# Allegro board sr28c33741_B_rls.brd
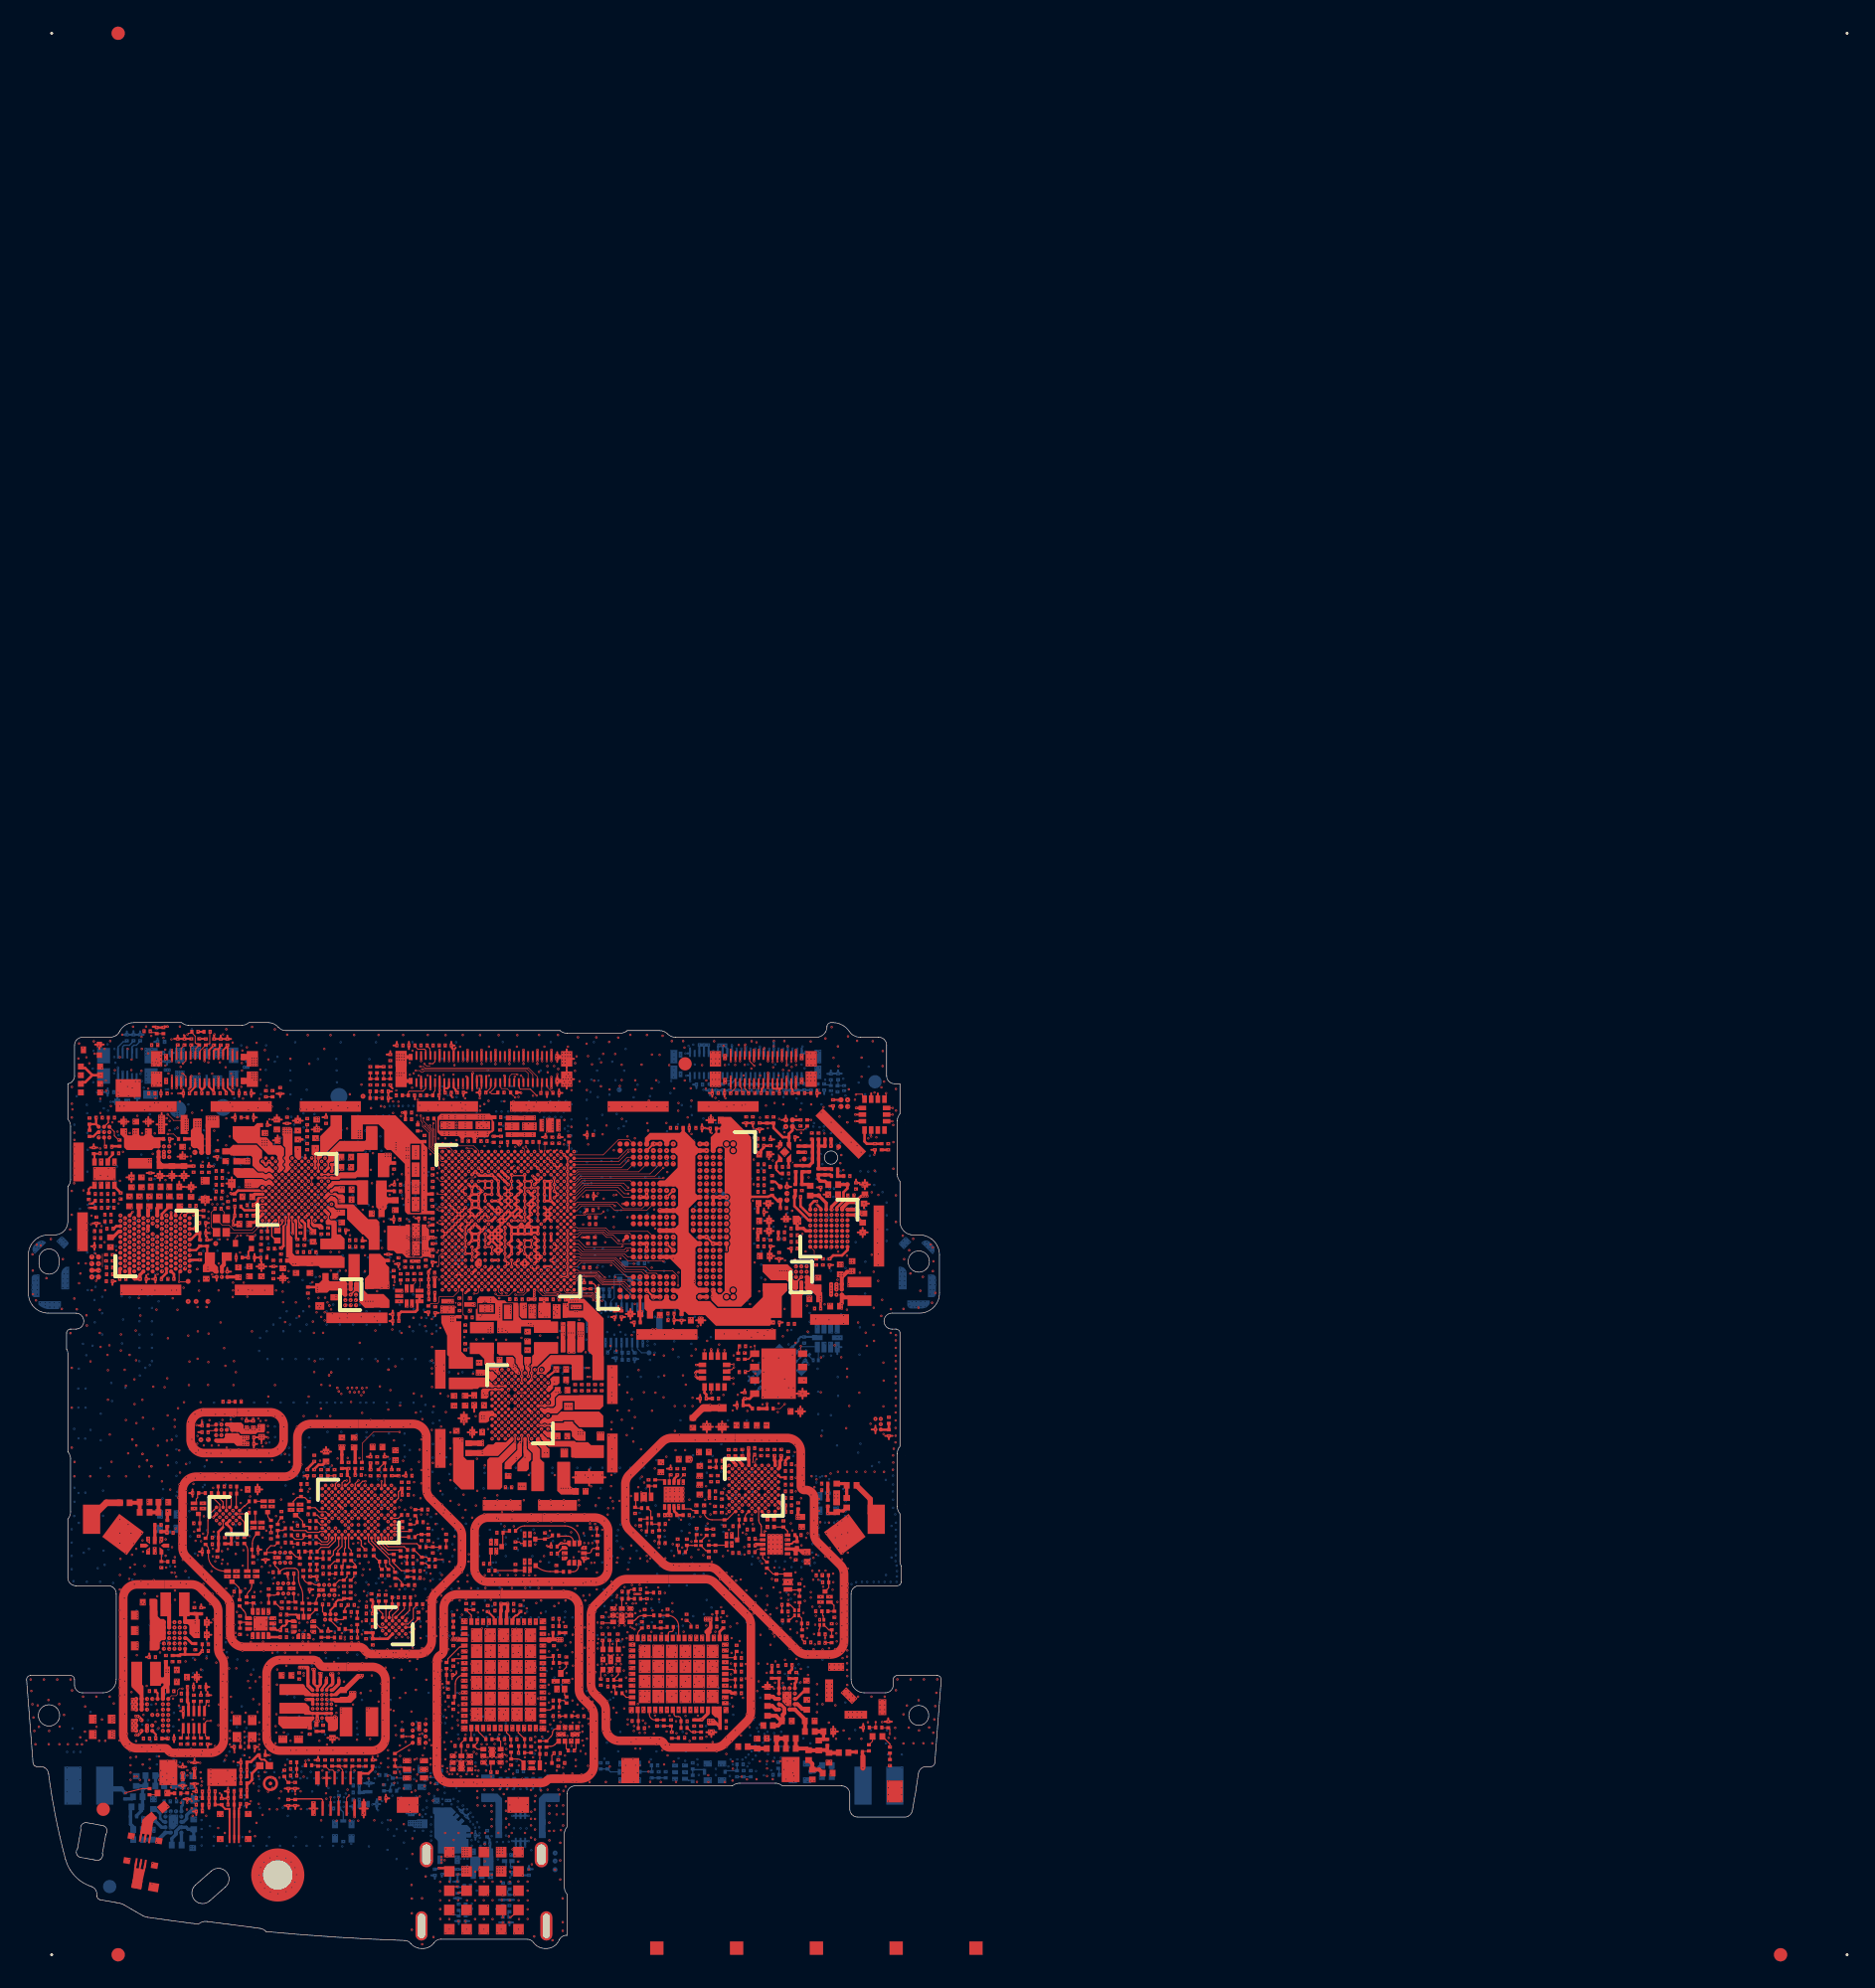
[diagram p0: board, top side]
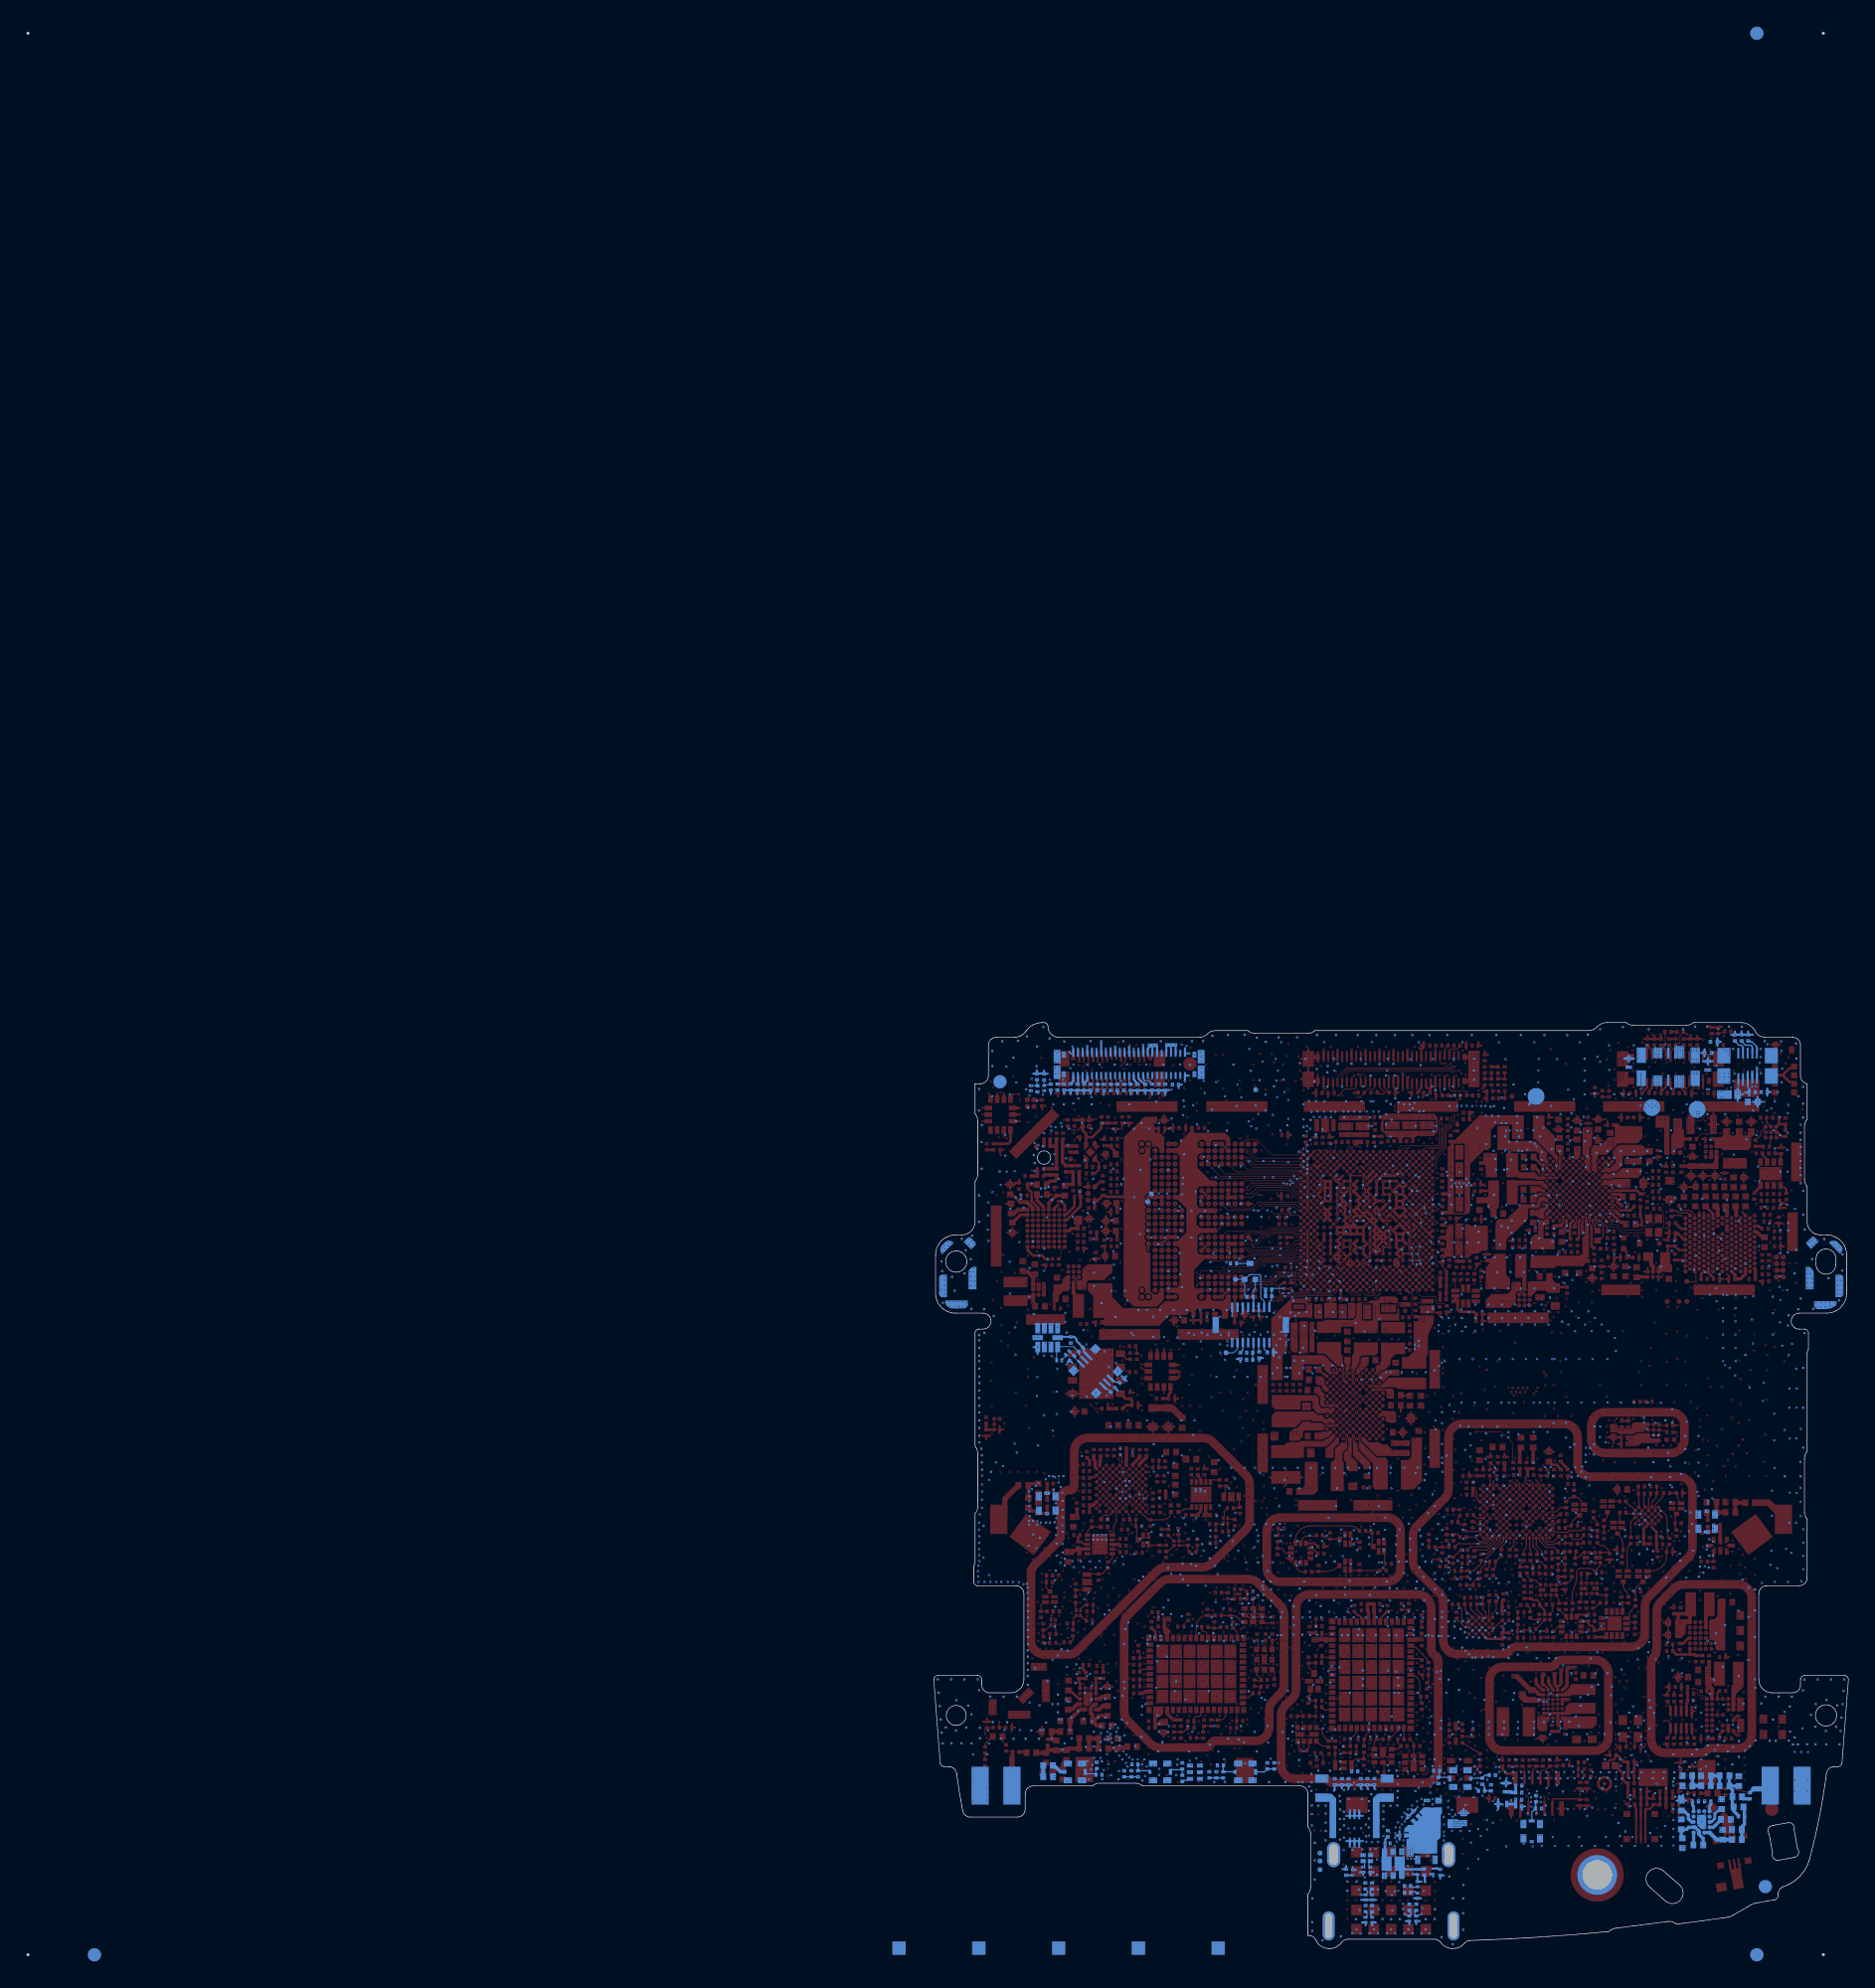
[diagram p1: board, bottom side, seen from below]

Outline 68.77 x 69.63 mm; copper layers: TOP, LAYER_2, LAYER_3, LAYER_4, LAYER_5, LAYER_6, LAYER_7, BOTTOM. Coordinates in mm from the lower left corner of the outline.

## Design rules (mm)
constraint set DEFAULT: min track width 0.05, pair gap 0.05
net group CXM_CMD: nets CXM_CMD<0> CXM_CMD<1>
net group DISP_SUP_DSI1_1_DP: nets DISP_SUB_DSI1<0> DISP_SUB_DSI1<1>
net group DISP_SUP_DSI1_2_DP: nets DISP_SUB_DSI1<2> DISP_SUB_DSI1<3>
net group DISP_SUP_DSI1_3_DP: nets DISP_SUB_DSI1<4> DISP_SUB_DSI1<5>
net group DP_MIPI_CSI_REAR_1: nets MIPI_CSI_REAR<0> MIPI_CSI_REAR<1>
net group DP_MIPI_CSI_REAR_2: nets MIPI_CSI_REAR<2> MIPI_CSI_REAR<3>
net group DP_MIPI_CSI_REAR_3: nets MIPI_CSI_REAR<4> MIPI_CSI_REAR<5>
net group DP_MIPI_CSI_REAR_4: nets MIPI_CSI_REAR<6> MIPI_CSI_REAR<7>
net group DP_MIPI_CSI_REAR_5: nets MIPI_CSI_REAR<8> MIPI_CSI_REAR<9>
net group DSBC_DP: nets USBC_DM USBC_DP
net group EBI0_DM: nets EBI0_DM<0> EBI0_DM<1>
net group EBI1_DM: nets EBI1_DM<0> EBI1_DM<1>
net group HIGH SPEED SSTX1: nets SSTX1_DM SSTX1_DP
net group HIGH SPEED SSTX2: nets SSTX2_DM SSTX2_DP
net group HIGH SPEED USB HS C: nets USB_HS_C_DM USB_HS_C_DP
net group MIPI_CSI2_1_DP: nets MIPI_CSI2_CLK_M MIPI_CSI2_CLK_P
net group MIPI_CSI2_2_DP: nets MIPI_CSI2_LANE0_M MIPI_CSI2_LANE0_P
net group MIPI_CSI2_3_DP: nets MIPI_CSI2_LANE1_M MIPI_CSI2_LANE1_P
net group MIPI_CSI2_4_DP: nets MIPI_CSI2_LANE2_M MIPI_CSI2_LANE2_P
net group MIPI_CSI2_5_DP: nets MIPI_CSI2_LANE3_M MIPI_CSI2_LANE3_P
net group MIPI_CSI_FRONT_1_DP: nets MIPI_CSI_FRONT<0> MIPI_CSI_FRONT<1>
net group MIPI_CSI_FRONT_2_DP: nets MIPI_CSI_FRONT<2> MIPI_CSI_FRONT<3>
net group MIPI_CSI_FRONT_3_DP: nets MIPI_CSI_FRONT<4> MIPI_CSI_FRONT<5>
net group MIPI_DSI0_1_DP: nets MIPI_DSI0<0> MIPI_DSI0<1>
net group MIPI_DSI0_2_DP: nets MIPI_DSI0<2> MIPI_DSI0<3>
net group MIPI_DSI0_3_DP: nets MIPI_DSI0<4> MIPI_DSI0<5>
net group MIPI_DSI0_4_DP: nets MIPI_DSI0<6> MIPI_DSI0<7>
net group MIPI_DSI0_5_DP: nets MIPI_DSI0<8> MIPI_DSI0<9>
net group MSS_CMD: nets MSS_CMD<0> MSS_CMD<1>
net group QLINK_CLK_DP: nets QLINK_CLK_M QLINK_CLK_P
net group QLINK_RX0_DP: nets QLINK_RX0_M QLINK_RX0_P
net group QLINK_RX1_DP: nets QLINK_RX1_M QLINK_RX1_P
net group QLINK_RX2_DP: nets QLINK_RX2_M QLINK_RX2_P
net group QLINK_TX_DP: nets QLINK_TX_M QLINK_TX_P
net group USBC_RX1_DP: nets USBC_RX1_DM USBC_RX1_DP
net group USBC_RX2_DP: nets USBC_RX2_DM USBC_RX2_DP
net group USBC_TX1_DP: nets USBC_TX1_DM USBC_TX1_DP
net group USBC_TX2_DP: nets USBC_TX2_DM USBC_TX2_DP
net group WL_BB_DP1: nets WL_BB<0> WL_BB<1>
net group WL_BB_DP2: nets WL_BB<2> WL_BB<3>
net group WL_BB_DP3: nets WL_BB<4> WL_BB<5>
net group WL_BB_DP4: nets WL_BB<6> WL_BB<7>
net group EBI0_CA: nets EBI0_CA<0> EBI0_CA<1> EBI0_CA<2> EBI0_CA<3> EBI0_CA<4> EBI0_CA<5>
net group EBI0_DQ: nets EBI0_DQ<0> EBI0_DQ<1> EBI0_DQ<2> EBI0_DQ<3> EBI0_DQ<4> EBI0_DQ<5> EBI0_DQ<6> EBI0_DQ<7> EBI0_DQ<8> EBI0_DQ<9> EBI0_DQ<10> EBI0_DQ<11> EBI0_DQ<12> EBI0_DQ<13> EBI0_DQ<14> EBI0_DQ<15>
net group EBI1_CA: nets EBI1_CA<0> EBI1_CA<1> EBI1_CA<2> EBI1_CA<3> EBI1_CA<4> EBI1_CA<5>
net group EBI1_DQ: nets EBI1_DQ<0> EBI1_DQ<1> EBI1_DQ<2> EBI1_DQ<3> EBI1_DQ<4> EBI1_DQ<5> EBI1_DQ<6> EBI1_DQ<7> EBI1_DQ<8> EBI1_DQ<9> EBI1_DQ<10> EBI1_DQ<11> EBI1_DQ<12> EBI1_DQ<13> EBI1_DQ<14> EBI1_DQ<15>
net group POWER_LN: nets B_PLUS BATT_PLUS USB_PWR
net group RF_50_OHM: nets GPS_LNA_IN_50R GPS_LNA_OUT_50R WTR0_GPS_A_50R
net group WL_CMD: nets WL_CMD<0> WL_CMD<1> WL_CMD<2> WL_CMD<3>

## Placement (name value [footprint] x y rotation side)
C100  100PF  [CAP0201-HT0_33_HD]  12.99 11.81 0 top
C102  .1UF  [CAP0201-HT0_33_HD]  11.5 11.06 0 bottom
C103  .1UF  [CAP0201-HT0_33_HD]  10.58 11.05 180 bottom
C105  100PF  [CAP0201-HT0_33_HD]  12.99 10.31 0 top
C110  100PF  [CAP0201-HT0_33_HD]  23.49 11.27 270 bottom
C112  10NH  [IND1005-HT0_6_HD]  12.56 9.34 270 bottom
C115  1.5e-005 uF  [CAP0402-HT0_55_HD]  11.29 7.78 0 bottom
C121  91NH  [IND1005-HT0_6_HD]  9.46 8.56 270 bottom
C124  4.3NH  [IND1005-HT0_6_HD]  8.26 10.65 0 bottom
C130  33PF  [CAP0201-HT0_33_HD]  30.97 13.37 180 bottom
C132  100PF  [CAP0201-HT0_33_HD]  26.88 12.08 270 bottom
C133  33PF  [CAP0201-HT0_33_HD]  26.78 13.04 180 bottom
C140  0  [RES0402-HT0_4_HD]  12.11 12.99 180 bottom
C141  6.2NH  [IND1005-HT0_6_HD]  12.1 12.23 180 bottom
C144  8.2NH  [IND1005-HT0_6_HD]  9.31 13 180 bottom
C172  100PF  [CAP0201-HT0_33_HD]  7.41 11.48 90 bottom
C174  1.5PF  [CAP0201-HT0_33_HD]  12.08 11.47 90 top
C200  100PF  [CAP0201-HT0_33_HD]  56.28 21.26 180 top
C202  .1UF  [CAP0201-HT0_33_HD]  56.58 20.55 270 top
C203  .1UF  [CAP0201-HT0_33_HD]  57.87 20.53 270 top
C205  100PF  [CAP0201-HT0_33_HD]  57.33 21.32 0 top
C210  100PF  [CAP0201-HT0_33_HD]  50.09 12.79 90 bottom
C212  100PF  [CAP0201-HT0_33_HD]  53.92 13.14 270 bottom
C213  100PF  [CAP0201-HT0_33_HD]  53.64 13.85 0 bottom
C214  0  [RES0402-HT0_4_HD]  55.76 16.77 0 top
C215  1.5e-005 uF  [CAP0402-HT0_55_HD]  55.71 17.87 90 top
C221  1e-006 uF  [CAP0402-HT0_55_HD]  58.89 17.11 180 top
C224  4.3NH  [IND1005-HT0_6_HD]  59.57 15.27 270 top
C230  33PF  [CAP0201-HT0_33_HD]  43.17 13.73 270 bottom
C232  100PF  [CAP0201-HT0_33_HD]  47.53 13.06 270 bottom
C233  33PF  [CAP0201-HT0_33_HD]  47.22 13.77 0 bottom
C240  0  [RES0402-HT0_4_HD]  53.87 15.18 0 top
C241  8.2NH  [IND1005-HT0_6_HD]  54.93 15.41 270 top
C244  6e-007 uF  [CAP0402-HT0_55_HD]  57.47 15.04 0 top
C250  12PF  [CAP0201-HT0_33_HD]  56.52 13.77 270 bottom
C260  0  [RES0402-HT0_4_HD]  60.18 13.76 0 bottom
C261  1.5e-006 uF  [CAP0402-HT0_55_HD]  60.18 12.92 0 bottom
C264  4e-007 uF  [CAP0402-HT0_55_HD]  58.8 14.54 90 top
C272  100PF  [CAP0201-HT0_33_HD]  62.62 14.78 0 top
C275  1.5PF  [CAP0201-HT0_33_HD]  64.92 13.98 90 top
C280  1.5PF  [CAP0201-HT0_33_HD]  64.79 16.83 270 top
C281  100PF  [CAP0201-HT0_33_HD]  63.14 16.62 180 top
C300  18PF  [CAP0201-HT0_33_HD]  60.02 34.96 0 top
C303  5.1NH  [IND1005-HT0_6_HD]  60.92 33.19 270 top
C305  8e-007 uF  [CAP0402-HT0_55_HD]  62.04 34.83 0 top
C400  18PF  [CAP0201-HT0_33_HD]  9.88 31.35 0 top
C402  4.7NH  [IND1005-HT0_6_HD]  10.29 32.8 180 top
C403  3e-007 uF  [CAP0402-HT0_55_HD]  10.29 33.56 180 top
C406  0  [RES0402-HT0_4_HD]  7.39 33.52 180 top
C501  100PF  [CAP0201-HT0_33_HD]  32.9 9.77 225 bottom
C502  1uF  [CAP0402-HT0_6_HD]  28.93 9.8 270 bottom
C503  0.1 uF  [CAP0402-HT0_55_HD]  30.82 10.75 270 bottom
C504  0.00015 uF  [CAP0201-HT0_33_HD]  33.52 8.5 180 bottom
C505  .22UF  [CAP0201-HT0_33_HD]  32.5 3.1 90 bottom
C506  .22UF  [CAP0201-HT0_33_HD]  33.02 3.1 90 bottom
C507  .22UF  [CAP0201-HT0_33_HD]  36.32 4.7 90 bottom
C508  .22UF  [CAP0201-HT0_33_HD]  35.82 4.7 90 bottom
C509  330nF  [CAP0201-HT0_33_HD]  33.15 4.71 0 bottom
C510  100PF  [CAP0201-HT0_33_HD]  10.34 64.31 0 top
C511  10 uF  [CAP1_2X0_7_HD]  7.2 63.67 0 bottom
C512  330nF  [CAP0201-HT0_33_HD]  33.15 4.21 0 bottom
C513  330nF  [CAP0201-HT0_33_HD]  36.31 3 90 bottom
C514  330nF  [CAP0201-HT0_33_HD]  35.81 3 90 bottom
C515  100PF  [CAP0201-HT0_33_HD]  15.91 62.49 0 top
C516  100PF  [CAP0201-HT0_33_HD]  15.91 41.12 180 top
C517  0.01 uF  [CAP0201-HT0_33_HD]  4.73 62.22 90 top
C518  .1UF  [CAP0201-HT0_33_HD]  4.74 61.3 270 top
C519  .1UF  [CAP0201-HT0_33_HD]  5.46 62.48 0 top
C520  1000PF  [CAP0201-HT0_33_HD]  27.76 47.19 0 top
C521  .1UF  [CAP0201-HT0_33_HD]  27.76 47.7 0 top
C522  0.00022 uF  [CAP0201-HT0_33_HD]  30.7 5.73 90 bottom
C523  0.00022 uF  [CAP0201-HT0_33_HD]  37.78 5.74 270 bottom
C1001  .022UF  [CAP0201-HT0_33_HD]  23.77 54.02 180 top
C1003  4.7PF  [CAP0201-HT0_33_HD]  24.52 53.27 180 top
C1004  4.7PF  [CAP0201-HT0_33_HD]  24.52 52.77 180 top
C1005  .1UF  [CAP0201-HT0_33_HD]  56.06 56.87 90 top
C1007  .1UF  [CAP0201-HT0_33_HD]  41.92 49.84 90 top
C1020  33PF  [CAP0201-HT0_33_HD]  45.72 44.57 90 bottom
C1021  33PF  [CAP0201-HT0_33_HD]  45.02 44.27 180 bottom
C1022  .01UF  [CAP0201-HT0_33_HD]  45.02 44.8 180 bottom
C1023  33PF  [CAP0201-HT0_33_HD]  43.6 49.55 180 bottom
C1024  .01UF  [CAP0201-HT0_33_HD]  43.6 49.05 180 bottom
C1049  1 uF  [CAP0201_HD]  30.53 51.84 90 top
C1050  22 uF  [CAP1_2X0_9_P3_HD]  34.31 61.91 90 top
C1051  22 uF  [CAP1_2X0_9_P3_HD]  31.67 61.91 270 top
C1052  22 uF  [CAP1_2X0_9_P3_HD]  33 61.91 270 top
C1053  1 uF  [CAP0201_HD]  33.46 60.72 0 top
C1054  1 uF  [CAP0201_HD]  35.43 62.51 180 top
C1057  22 uF  [CAP1_2X0_9_P3_HD]  29.26 59.87 180 top
C1058  22 uF  [CAP1_2X0_9_P3_HD]  29.26 58.57 180 top
C1059  22 uF  [CAP1_2X0_9_P3_HD]  29.26 57.27 0 top
C1060  22 uF  [CAP1_2X0_9_P3_HD]  29.25 55.97 180 top
C1064  1 uF  [CAP0201_HD]  30.53 53.71 270 top
C1067  1 uF  [CAP0201_HD]  30.54 55.58 270 top
C1068  1 uF  [CAP0201_HD]  30.48 56.52 90 top
C1070  1 uF  [CAP0201_HD]  30.53 52.77 270 top
C1071  22 uF  [CAP1_2X0_9_P3_HD]  29.28 52.66 0 top
C1072  22 uF  [CAP1_2X0_9_P3_HD]  29.28 53.98 0 top
C1075  22 uF  [CAP1_2X0_9_P3_HD]  31.66 48.05 270 top
C1076  22 uF  [CAP1_2X0_9_P3_HD]  39.36 61.91 180 top
C1077  1 uF  [CAP0201_HD]  32.56 48.68 90 top
C1078  1 uF  [CAP0201_HD]  35.68 60.85 270 top
C1080  .1UF  [CAP0201-HT0_33_HD]  27.89 57.45 0 top
C1090  1 uF  [CAP0201_HD]  29.72 54.91 0 top
C1091  1 uF  [CAP0201_HD]  30.46 50.32 0 top
C1092  1 uF  [CAP0201_HD]  42.22 53.25 90 top
C1093  1 uF  [CAP0201_HD]  30.54 58.41 270 top
C1094  1 uF  [CAP0201_HD]  37.49 48.82 180 top
C1095  1 uF  [CAP0201_HD]  30.02 51.54 270 top
C1096  1 uF  [CAP0201_HD]  35.61 61.78 270 top
C1097  1 uF  [CAP0201_HD]  42.57 54.48 180 top
C1098  1 uF  [CAP0201_HD]  48.65 61.71 180 top
C1099  1 uF  [CAP0201_HD]  44.23 47.72 90 top
C1100  1 uF  [CAP0201_HD]  28.64 50.51 270 top
C1101  1 uF  [CAP0201_HD]  44.74 47.72 90 top
C1102  1 uF  [CAP0201_HD]  30.54 57.46 270 top
C1103  1 uF  [CAP0201_HD]  27.84 54.83 0 top
C1104  .1UF  [CAP0201-HT0_33_HD]  30.45 50.83 0 top
C1105  1 uF  [CAP0201_HD]  30.48 48.81 0 top
C1106  1 uF  [CAP0201_HD]  30.73 48.03 90 top
C1107  22 uF  [CAP1_2X0_9_P3_HD]  37.81 61.83 270 top
C1108  22 uF  [CAP1_2X0_9_P3_HD]  36.19 47.87 0 top
C1109  22 uF  [CAP1_2X0_9_P3_HD]  34.58 48.13 270 top
C1110  22 uF  [CAP1_2X0_9_P3_HD]  36.51 61.83 270 top
C1111  1 uF  [CAP0201_HD]  39.36 48.82 180 top
C1112  1 uF  [CAP0201_HD]  38.43 48.82 0 top
C1114  22 uF  [CAP1_2X0_9_P3_HD]  39.86 47.91 0 top
C1115  22 uF  [CAP1_2X0_9_P3_HD]  38.03 47.92 180 top
C1116  22 uF  [CAP1_2X0_9_P3_HD]  40.96 45.31 0 top
C1117  22 uF  [CAP1_2X0_9_P3_HD]  40.96 46.61 180 top
C1119  1 uF  [CAP0201_HD]  42.73 53.25 90 top
C1120  1 uF  [CAP0201_HD]  50.56 61.71 180 top
C1121  1 uF  [CAP0201_HD]  55.95 60.61 270 top
C1122  1 uF  [CAP0201_HD]  39.53 60.78 270 top
C1123  1 uF  [CAP0201_HD]  37.38 60.66 180 top
C1124  1 uF  [CAP0201_HD]  42.37 55.53 180 top
C1126  1 uF  [CAP0201_HD]  29.48 51.46 90 top
C1127  1 uF  [CAP0201_HD]  28.97 51.46 90 top
C1128  1 uF  [CAP0201_HD]  40.04 60.78 270 top
C1129  1 uF  [CAP0201_HD]  35.13 60.85 270 top
C1130  .1UF  [CAP0201-HT0_33_HD]  27.35 65.17 90 top
C1131  .1UF  [CAP0201-HT0_33_HD]  25.85 66.08 270 top
C1132  1 uF  [CAP0201_HD]  36.4 60.66 0 top
C1133  4.3 uF  [CAP1X0_5-HT0_5_P3_HD]  33.34 48.43 90 top
C1140  1 uF  [CAP0201_HD]  40.29 48.81 0 top
C1141  4.3 uF  [CAP1X0_5-HT0_5_P3_HD]  41.32 48.25 90 top
C1150  1 uF  [CAP0201_HD]  32.56 47.74 270 top
C1151  1 uF  [CAP0201_HD]  30.54 54.65 270 top
C1152  1 uF  [CAP0201_HD]  42.41 56.58 180 top
C1154  1 uF  [CAP0201_HD]  28.47 51.46 270 top
C1155  1 uF  [CAP0201_HD]  42.12 51.21 0 top
C1156  1 uF  [CAP0201_HD]  30.46 49.81 0 top
C1157  1 uF  [CAP0201_HD]  34.4 60.72 0 top
C1159  1 uF  [CAP0201_HD]  36.56 48.83 0 top
C1164  1 uF  [CAP0201_HD]  30.47 49.31 0 top
C1511  33PF  [CAP0201-HT0_33_HD]  22.97 13.94 270 top
C1512  33PF  [CAP0201-HT0_33_HD]  20.08 13.5 0 top
C1513  33PF  [CAP0201-HT0_33_HD]  25 13.94 270 top
C1514  33PF  [CAP0201-HT0_33_HD]  19.69 12.26 90 top
C1515  33PF  [CAP0201-HT0_33_HD]  21.92 13.94 270 top
C1516  33PF  [CAP0201-HT0_33_HD]  24.79 11.73 0 bottom
C1517  18PF  [CAP0201-HT0_33_HD]  26.02 13.94 270 top
C1518  18PF  [CAP0201-HT0_33_HD]  26.79 11.29 180 top
C1532  33PF  [CAP0201-HT0_33_HD]  24.79 10.69 0 bottom
C1601  2.2UF  [CAP0402-HT0_55_HD]  55.41 56.04 180 top
C1602  2.2UF  [CAP0402-HT0_55_HD]  55.46 54.72 180 top
C1603  1 uF  [CAP0201_HD]  55.22 55.38 180 top
C1604  .1UF  [CAP0201-HT0_33_HD]  55.23 58.45 180 top
C1605  2.2UF  [CAP0402-HT0_55_HD]  55.46 53.96 180 top
C1606  1 uF  [CAP0201_HD]  55.22 53.32 180 top
C1607  2.2UF  [CAP0402-HT0_55_HD]  45.78 47.72 0 top
C1608  2.2UF  [CAP0402-HT0_55_HD]  51.83 62.29 0 top
C1609  1 uF  [CAP0201_HD]  51.64 61.66 0 top
C1610  1 uF  [CAP0201_HD]  45.92 47.08 0 top
C1611  1 uF  [CAP0201_HD]  55.23 56.9 180 top
C1612  2.2UF  [CAP0402-HT0_55_HD]  50.32 47.24 180 top
C1613  2.2UF  [CAP0402-HT0_55_HD]  55.46 59.73 180 top
C1614  1 uF  [CAP0201_HD]  48.46 47.75 180 top
C1615  .1UF  [CAP0201-HT0_33_HD]  55.23 57.9 180 top
C1616  1 uF  [CAP0201_HD]  42.38 61.18 0 top
C1617  1 uF  [CAP0201_HD]  55.22 52.8 180 top
C1618  1 uF  [CAP0201_HD]  49.25 47.47 90 top
C1619  1 uF  [CAP0201_HD]  55.23 58.97 180 top
C1620  1 uF  [CAP0201_HD]  49.6 61.7 180 top
C1621  1 uF  [CAP0201_HD]  56.38 47.08 180 top
C1622  4.7uF  [CAP0402-HT0_65_HD]  47.25 47.63 180 top
C1623  4.7uF  [CAP0402-HT0_65_HD]  55.51 52.08 180 top
C1624  1 uF  [CAP0201_HD]  55.94 53.04 90 top
C1632  1 uF  [CAP0201_HD]  56.59 52.11 90 top
C1633  1 uF  [CAP0201_HD]  55.23 57.4 180 top
C2000  1000PF  [CAP0201-HT0_33_HD]  14.4 55.64 180 top
C2001  .1UF  [CAP0201-HT0_33_HD]  18.41 52.63 0 top
C2002  1 uF  [CAP0201_HD]  22.67 53.96 270 top
C2003  .1UF  [CAP0201-HT0_33_HD]  21.1 60.3 270 top
C2004  100PF  [CAP0201-HT0_33_HD]  17.63 52.72 270 top
C2018  .1UF  [CAP0201-HT0_33_HD]  15.99 51.96 0 top
C2020  .1UF  [CAP0201-HT0_33_HD]  10.29 69.03 270 top
C2108  .1UF  [CAP0201-HT0_33_HD]  22.52 62.28 90 top
C2253  2.2 uF  [CAP0402-HT0_55_HD]  23.7 54.97 90 top
C2254  2.2 uF  [CAP0402-HT0_55_HD]  21.73 60.57 270 top
C2255  2.2 uF  [CAP0402-HT0_55_HD]  24.04 59.52 180 top
C2256  2.2 uF  [CAP0402-HT0_55_HD]  24.04 58.75 180 top
C2257  2.2 uF  [CAP0402-HT0_55_HD]  24.07 56.32 180 top
C2258  2.2 uF  [CAP0402-HT0_55_HD]  24.07 57.07 180 top
C2262  100PF  [CAP0201-HT0_33_HD]  13.18 58.6 90 top
C2263  10 uF  [CAP1_2X0_7_HD]  50.1 39.53 90 top
C2270  10 uF  [CAP1_2X0_7_HD]  8.22 61.81 270 top
C2271  100PF  [CAP0201-HT0_33_HD]  29.92 60.91 270 top
C2272  100PF  [CAP0201-HT0_33_HD]  19.34 51.73 0 top
C2274  100PF  [CAP0201-HT0_33_HD]  27.89 56.94 180 top
C2275  10 uF  [CAP1_2X0_7_HD]  12.37 56.89 270 top
C2276  10 uF  [CAP1_2X0_7_HD]  20.4 60.47 270 top
C2277  100PF  [CAP0201-HT0_33_HD]  10.53 60.88 180 top
C2278  100PF  [CAP0201-HT0_33_HD]  27.63 58.84 90 top
C2279  10 uF  [CAP1_2X0_7_HD]  10.93 58.47 90 top
C2281  100PF  [CAP0201-HT0_33_HD]  12.56 58.61 90 top
C2282  10uF  [CAP1_2X0_7_HD]  12.43 20.41 180 top
C2283  10 uF  [CAP1_2X0_7_HD]  17.66 50.92 270 top
C2284  10 uF  [CAP1_2X0_7_HD]  16.76 50.92 270 top
C2285  10 uF  [CAP1_2X0_7_HD]  19.55 20.54 0 top
C2286  10 uF  [CAP1_2X0_7_HD]  21.81 61.96 90 top
C2287  10 uF  [CAP1_2X0_7_HD]  9.16 61.81 270 top
C2288  10 uF  [CAP1_2X0_7_HD]  57.82 40.39 180 top
C2290  22 uF  [CAP1_2X0_7_HD]  20.26 51.17 90 top
C2291  22 uF  [CAP1_2X0_7_HD]  27.73 55.9 90 top
C2292  22 uF  [CAP1_2X0_7_HD]  26.32 55.26 0 top
C2294  22 uF  [CAP1_2X0_7_HD]  21.31 51.17 90 top
C2295  10 uF  [CAP1_2X0_7_HD]  11.84 58.47 90 top
C2296  10 uF  [CAP1_2X0_7_HD]  10.03 58.47 90 top
C2319  1 uF  [CAP0201_HD]  17.89 53.93 180 top
C2320  4.7 uF  [CAP0402-HT0_55_HD]  18.86 53.61 90 top
C2330  1 uF  [CAP0201_HD]  15.88 55.11 0 top
C2331  1 uF  [CAP0201_HD]  20.38 53.1 90 top
C2332  1 uF  [CAP0201_HD]  16.82 55.9 0 top
C2333  .1UF  [CAP0201-HT0_33_HD]  17.84 51.95 0 top
C2334  .1UF  [CAP0201-HT0_33_HD]  18.56 51.52 90 top
C2335  2.2 uF  [CAP0201_HD]  20.6 54.04 90 top
C2336  4.7 uF  [CAP0402-HT0_55_HD]  21.54 53.52 90 top
C2337  2.2 uF  [CAP0201_HD]  16.81 55.11 0 top
C2338  2.2 uF  [CAP0201_HD]  20.9 53.11 90 top
C2339  4.7 uF  [CAP0402-HT0_55_HD]  16.37 54.48 0 top
C2340  2.2 uF  [CAP0201_HD]  22.17 53.96 90 top
C2352  1 uF  [CAP0201_HD]  17.89 53.43 0 top
C2353  1 uF  [CAP0201_HD]  19.13 52.45 90 top
C2354  1 uF  [CAP0201_HD]  21.53 52.37 180 top
C2355  2.2 uF  [CAP0402-HT0_55_HD]  34.03 41.6 0 top
C2356  2.2 uF  [CAP0402-HT0_55_HD]  40.2 43.55 180 top
C2357  2.2 uF  [CAP0402-HT0_55_HD]  37.68 44.63 270 top
C2358  2.2 uF  [CAP0402-HT0_55_HD]  35.93 44.25 0 top
C2359  2.2 uF  [CAP0402-HT0_55_HD]  34.04 43.68 270 top
C2360  22 uF  [CAP0603-HT0_6_HD]  51.15 39.94 270 top
C2361  22 uF  [CAP0603-HT0_6_HD]  52.3 39.94 270 top
C2362  22 uF  [CAP0603-HT0_6_HD]  13.43 57.03 270 top
C2363  22 uF  [CAP0603-HT0_6_HD]  22.05 49.03 270 top
C2364  22 uF  [CAP0603-HT0_6_HD]  33.6 39.87 180 top
C2370  1 uF  [CAP0201_HD]  41.25 42.18 90 top
C2371  1 uF  [CAP0201_HD]  42.75 42.18 270 top
C2372  4.7 uF  [CAP0402-HT0_55_HD]  37.68 46.02 270 top
C2374  4.7 uF  [CAP0402-HT0_55_HD]  32.98 41.2 270 top
C2375  1 uF  [CAP0201_HD]  5.05 60 270 top
C2376  4.7 uF  [CAP0402-HT0_55_HD]  34.03 40.85 0 top
C2377  1 uF  [CAP0201_HD]  41.75 42.18 90 top
C2380  4.7 uF  [CAP0402-HT0_55_HD]  19.27 50.78 90 top
C2381  1 uF  [CAP0201_HD]  20.6 52.37 180 top
C2382  1 uF  [CAP0201_HD]  14.49 57.95 0 top
C2383  1 uF  [CAP0201_HD]  15.89 55.8 0 top
C2384  1 uF  [CAP0201_HD]  14.49 56.93 0 top
C2385  4.7 uF  [CAP0402-HT0_55_HD]  16.6 56.53 0 top
C2386  1 uF  [CAP0201_HD]  15.65 56.52 90 top
C2396  1 uF  [CAP0201_HD]  27.19 51.97 270 top
C2397  2.2 uF  [CAP0201_HD]  32.99 46.65 90 top
C2398  .1UF  [CAP0201-HT0_33_HD]  32.99 45.25 90 top
C2400  4.7 uF  [CAP0603-HT1_HD]  16.14 57.53 0 top
C2402  0.027 uF  [CAP0402-HT0_55_HD]  14.97 59.58 270 top
C2403  4.7uF  [CAP0402-HT0_65_HD]  18.82 61.96 270 top
C2404  10 uF  [CAP1_2X0_7_HD]  17.92 60.96 270 top
C2405  100PF  [CAP0201-HT0_33_HD]  17.88 61.92 180 top
C2407  1 uF  [CAP0201_HD]  14.49 57.43 0 top
C2408  0.1 uF  [CAP0201-HT0_33_HD]  14.49 58.47 0 top
C2409  10 uF  [CAP1_2X0_7_HD]  19.25 60.77 0 top
C2410  4.7uF  [CAP0402-HT0_65_HD]  20.4 61.88 270 top
C2412  2.2uF  [CAP0402-HT0_6_HD]  16.56 58.83 270 top
C2416  10 uF  [CAP1_2X0_7_HD]  11.73 59.92 90 top
C2417  10 uF  [CAP1_2X0_7_HD]  7.3 61.81 270 top
C2418  100nF  [CAP0201-HT0_33_HD]  13.42 38.83 0 top
C2420  .1UF  [CAP0201-HT0_33_HD]  43.25 42.18 270 top
C2421  1 uF  [CAP0201_HD]  42.25 42.18 270 top
C2422  2.2uF  [CAP0402-HT0_6_HD]  15.8 58.83 270 top
C2430  0.00018 uF  [CAP0201-HT0_33_HD]  16.54 39.44 270 top
C2431  0.00015 uF  [CAP0201-HT0_33_HD]  17.04 39.44 270 top
C2432  0.00018 uF  [CAP0201-HT0_33_HD]  16.86 37.94 180 top
C2433  0.00015 uF  [CAP0201-HT0_33_HD]  16.86 38.44 180 top
C2434  1uF  [CAP0402-HT0_6_HD]  17.67 38.84 90 top
C2451  2.2 uF  [CAP0402-HT0_55_HD]  40.2 42.77 180 top
C2452  22 uF  [CAP0603-HT0_6_HD]  40.75 40.06 270 top
C2453  22 uF  [CAP0603-HT0_6_HD]  42.45 38.53 180 top
C2455  2.2 uF  [CAP0402-HT0_55_HD]  40.3 41.99 180 top
C2501  10 uF  [CAP1_2X0_7_HD]  33.89 38.82 0 top
C2502  10 uF  [CAP1_2X0_7_HD]  32.14 41.19 90 top
C2503  22 uF  [CAP0603-HT0_6_HD]  37.26 35.47 90 top
C2504  10 uF  [CAP1_2X0_7_HD]  40.29 38.53 180 top
C2505  22 uF  [CAP0603-HT0_6_HD]  39.72 37.26 180 top
C2506  10 uF  [CAP1_2X0_7_HD]  36.21 35.9 90 top
C2507  10 uF  [CAP1_2X0_7_HD]  41.67 34.38 180 top
C2508  10 uF  [CAP1_2X0_7_HD]  34.14 37.63 270 top
C2509  10 uF  [CAP1_2X0_7_HD]  33.24 37.63 270 top
C2510  10 uF  [CAP1_2X0_7_HD]  32.32 38.56 270 top
C2512  .1UF  [CAP0201-HT0_33_HD]  36.24 34.68 0 top
C2560  4.7uF  [CAP0402-HT0_65_HD]  23.11 49.34 90 top
C2561  4.7uF  [CAP0402-HT0_65_HD]  22.85 50.54 180 top
C2562  .1UF  [CAP0201-HT0_33_HD]  21.16 49.51 90 top
C2563  22 uF  [CAP0603-HT0_6_HD]  26.93 49.18 270 top
C2564  22 uF  [CAP0603-HT0_6_HD]  25.78 49.18 270 top
C2570  4.7uF  [CAP0402-HT0_65_HD]  59.24 48.85 0 top
C2571  4.7uF  [CAP0402-HT0_65_HD]  59.52 50.07 270 top
C2572  .1UF  [CAP0201-HT0_33_HD]  59.48 48.12 0 top
C2573  22 uF  [CAP0603-HT0_6_HD]  56.85 50.45 90 top
C2574  22 uF  [CAP0603-HT0_6_HD]  55.7 50.45 90 top
C3001  4.7 uF  [CAP0402_1_2X0_7-HT0_65_HD]  27.74 37.1 270 top
C3002  .1UF  [CAP0201-HT0_33_HD]  25.48 29.76 270 top
C3003  .1UF  [CAP0201-HT0_33_HD]  22.15 35.78 90 top
C3004  .1UF  [CAP0201-HT0_33_HD]  27.46 35.78 270 top
C3005  4.7 uF  [CAP0402_1_2X0_7-HT0_65_HD]  26.39 37.71 0 top
C3006  .1UF  [CAP0201-HT0_33_HD]  27.96 35.78 270 top
C3007  4.7 uF  [CAP0402_1_2X0_7-HT0_65_HD]  22.52 36.99 270 top
C3008  .1UF  [CAP0201-HT0_33_HD]  24.98 29.76 90 top
C3009  .1UF  [CAP0201-HT0_33_HD]  25.86 36.75 270 top
C3010  .1UF  [CAP0201-HT0_33_HD]  25.86 35.78 90 top
C3011  .1UF  [CAP0201-HT0_33_HD]  23.89 35.6 0 top
C3012  .1UF  [CAP0201-HT0_33_HD]  24.21 36.33 270 top
C3013  4.7 uF  [CAP0402_1_2X0_7-HT0_65_HD]  23.7 38.06 270 top
C3014  .1UF  [CAP0201-HT0_33_HD]  24.93 35.61 180 top
C3015  4.7 uF  [CAP0402_1_2X0_7-HT0_65_HD]  24.63 38.05 270 top
C3016  .1UF  [CAP0201-HT0_33_HD]  28.72 34.83 90 top
C3018  .1UF  [CAP0201-HT0_33_HD]  21.61 35.78 90 top
C3102  10PF  [CAP0201-HT0_33_HD]  23.16 35.78 270 top
C3121  .1UF  [CAP0201-HT0_33_HD]  28.75 35.55 0 top
C3122  .1UF  [CAP0201-HT0_33_HD]  21.63 36.86 270 top
C3123  .1UF  [CAP0201-HT0_33_HD]  21.11 35.78 90 top
C3124  .47UF  [CAP0201-HT0_33_HD]  28.47 34.12 180 top
C3125  .1UF  [CAP0201-HT0_33_HD]  28.21 34.83 270 top
C4000  2.2 uF  [CAP0201_HD]  53.29 37.28 270 top
C4001  4.7 uF  [CAP0402_1_2X0_7-HT0_65_HD]  49.41 36.79 0 top
C4002  0.01 uF  [CAP0201-HT0_33_HD]  57.29 33.88 180 top
C4003  0.01 uF  [CAP0201-HT0_33_HD]  52.29 34.03 270 top
C4004  100PF  [CAP0201-HT0_33_HD]  57.29 36.42 180 top
C4005  100PF  [CAP0201-HT0_33_HD]  51.57 33.88 180 top
C4006  0.01 uF  [CAP0201-HT0_33_HD]  57.29 34.38 180 top
C4007  .22UF  [CAP0201-HT0_33_HD]  54.52 37.63 180 top
C4008  0.01 uF  [CAP0201-HT0_33_HD]  54.52 37.13 180 top
C4009  0.01 uF  [CAP0201-HT0_33_HD]  56.24 37.29 270 top
C4010  0.01 uF  [CAP0201-HT0_33_HD]  57.29 34.88 180 top
C4011  .1UF  [CAP0201-HT0_33_HD]  56.74 37.29 270 top
C4012  4.7 uF  [CAP0402_1_2X0_7-HT0_65_HD]  53.75 39.35 0 top
C4013  .47UF  [CAP0201-HT0_33_HD]  52.79 37.28 270 top
C4014  10 uF  [CAP0402_1_2X0_7-HT0_65_HD]  50.93 37.33 0 top
C4015  .47UF  [CAP0201-HT0_33_HD]  51.47 35.33 90 top
C4016  .47UF  [CAP0201-HT0_33_HD]  51.97 35.33 90 top
C4017  10 uF  [CAP0402_1_2X0_7-HT0_65_HD]  50.62 34.51 90 top
C4018  4.7 uF  [CAP0402_1_2X0_7-HT0_65_HD]  50.62 35.92 270 top
C4019  0.01 uF  [CAP0201-HT0_33_HD]  51.77 33.02 90 top
C4020  0.01 uF  [CAP0201-HT0_33_HD]  52.28 33.02 90 top
C4021  10 uF  [CAP0402_1_2X0_7-HT0_65_HD]  55.28 39.34 180 top
C4022  4.7 uF  [CAP0402_1_2X0_7-HT0_65_HD]  58.29 32.08 90 top
C4023  0.01 uF  [CAP0201-HT0_33_HD]  57.29 32.83 180 top
C4024  0.01 uF  [CAP0201-HT0_33_HD]  58.02 33.28 270 top
C4025  0.01 uF  [CAP0201-HT0_33_HD]  57.29 33.33 180 top
C4026  .1UF  [CAP0201-HT0_33_HD]  55.73 37.29 270 top
C4027  0.01 uF  [CAP0201-HT0_33_HD]  55.23 37.29 270 top
C4032  100PF  [CAP0201-HT0_33_HD]  53.81 37.29 270 top
C4033  39PF  [CAP0201-HT0_33_HD]  51.37 36.41 270 top
C4034  22PF  [CAP0201-HT0_33_HD]  52.08 36.18 180 top
C4040  6.8PF  [CAP0201-HT0_33_HD]  47.27 35.01 270 top
C4043  3.3PF  [CAP0201-HT0_33_HD]  46.48 33.12 0 top
C4047  33PF  [CAP0201-HT0_33_HD]  47.57 31.21 270 top
C4050  6.8PF  [CAP0201-HT0_33_HD]  55.67 28.83 270 top
C4053  3.3PF  [CAP0201-HT0_33_HD]  58.12 26.25 270 top
C4057  33PF  [CAP0201-HT0_33_HD]  58.31 23.73 270 top
C4060  18PF  [CAP0201-HT0_33_HD]  60.07 28.07 0 top
C4063  18PF  [CAP0201-HT0_33_HD]  60.03 25.36 180 top
C4067  33PF  [CAP0201-HT0_33_HD]  60.54 23.23 270 top
C4070  18PF  [CAP0201-HT0_33_HD]  53.81 32.26 180 top
C4073  18PF  [CAP0201-HT0_33_HD]  51.3 30.1 270 top
C4077  33PF  [CAP0201-HT0_33_HD]  49.31 29.81 180 top
C4082  4.7 uF  [CAP0402_1_2X0_7-HT0_65_HD]  58.7 29.45 90 top
C4083  .1UF  [CAP0201-HT0_33_HD]  57.84 29.46 90 top
C4084  1 uF  [CAP0201_HD]  58.01 31.09 180 top
C4085  .1UF  [CAP0201-HT0_33_HD]  54.55 30.31 180 top
C4086  10PF  [CAP0201-HT0_33_HD]  54.54 29.81 0 top
C4087  10PF  [CAP0201-HT0_33_HD]  54.55 30.81 0 top
C4092  4.7 uF  [CAP0402_1_2X0_7-HT0_65_HD]  47.7 36.2 270 top
C4093  .1UF  [CAP0201-HT0_33_HD]  48.93 35.85 270 top
C4094  1 uF  [CAP0201_HD]  49.6 32.59 180 top
C4095  .1UF  [CAP0201-HT0_33_HD]  47.76 32.59 180 top
C4096  10PF  [CAP0201-HT0_33_HD]  49.43 35.85 270 top
C4097  10PF  [CAP0201-HT0_33_HD]  48.43 35.85 270 top
C4100  4.7 uF  [CAP1_2X0_7_HD]  57.48 54.86 0 top
C4101  .1UF  [CAP0201-HT0_33_HD]  57.72 54.15 0 top
C4102  1 uF  [CAP0201_HD]  57.73 53.14 0 top
C4103  4.7 uF  [CAP1_2X0_7_HD]  62.97 55.65 270 top
C4105  .1UF  [CAP0201-HT0_33_HD]  60.38 51.63 90 top
C4108  1 uF  [CAP0201_HD]  57.73 53.64 0 top
C4110  2.2UF  [CAP0402-HT0_55_HD]  60.65 56.7 0 top
C4115  1 uF  [CAP0201_HD]  62.37 57.35 270 top
C4121  4.7 uF  [CAP1_2X0_7_HD]  60.8 48.3 0 top
C4124  4.7 uF  [CAP1_2X0_7_HD]  61.18 51.07 270 top
C4125  4.7 uF  [CAP1_2X0_7_HD]  62.08 51.32 270 top
C4126  .1UF  [CAP0402-HT0_55_HD]  63.03 57.09 270 top
C4130  .1UF  [CAP0201-HT0_33_HD]  61.98 56.63 180 top
C4131  2.2UF  [CAP0402-HT0_55_HD]  62.87 54.22 90 top
C4151  0.00056 uF  [CAP0201-HT0_33_HD]  59.71 57.47 90 top
C4152  10PF  [CAP0201-HT0_33_HD]  60.05 58.41 270 top
C4153  150PF  [CAP0201-HT0_33_HD]  59.54 58.41 270 top
C4154  0.00039 uF  [CAP0201-HT0_33_HD]  59.33 59.88 0 top
C4155  1.8PF  [CAP0201-HT0_33_HD]  59.33 60.38 0 top
C4156  33PF  [CAP0201-HT0_33_HD]  60.25 60.85 180 top
C4157  82PF  [CAP0201-HT0_33_HD]  60.25 60.34 180 top
C4159  0  [RES0201-HT0_28_HD]  61.68 58.09 180 top
C4161  0.00056 uF  [CAP0201-HT0_33_HD]  58.3 57.23 270 top
C4162  10PF  [CAP0201-HT0_33_HD]  58.35 58.65 270 top
C4163  150PF  [CAP0201-HT0_33_HD]  58.86 58.65 270 top
C4165  3.9e-005 uF  [CAP0201-HT0_33_HD]  57.97 56.52 0 top
C4166  33PF  [CAP0201-HT0_33_HD]  58.03 60.11 90 top
C4167  82PF  [CAP0201-HT0_33_HD]  58.53 60.11 90 top
C4169  0  [RES0201-HT0_28_HD]  57.8 57.23 90 top
C4214  1 uF  [CAP0201_HD]  54 41.58 270 top
C4215  .1UF  [CAP0201-HT0_33_HD]  53.65 40.85 0 top
C4501  100PF  [CAP0201-HT0_33_HD]  13.95 11.32 0 top
C4502  100PF  [CAP0201-HT0_33_HD]  15.38 11.32 0 top
C4503  100PF  [CAP0201-HT0_33_HD]  16.31 10.87 180 top
C4504  18PF  [CAP0201-HT0_33_HD]  15.38 11.82 0 top
C4505  18PF  [CAP0201-HT0_33_HD]  13.95 11.82 0 top
C4506  .1UF  [CAP0201-HT0_33_HD]  13.95 10.82 0 top
C4520  .1UF  [CAP0201-HT0_33_HD]  16.34 12.94 0 top
C4521  18PF  [CAP0201-HT0_33_HD]  16.34 11.92 0 top
C4522  100PF  [CAP0201-HT0_33_HD]  16.34 11.42 0 top
C4523  100PF  [CAP0201-HT0_33_HD]  16.34 13.99 0 top
C4524  18PF  [CAP0201-HT0_33_HD]  16.34 13.44 0 top
C4600  .1UF  [CAP0201-HT0_33_HD]  9.47 19.36 0 top
C4601  .1UF  [CAP0201-HT0_33_HD]  10.85 19.35 180 top
C4602  10uF  [CAP1_2X0_7_HD]  10.93 20.05 180 top
C4603  .1UF  [CAP0201-HT0_33_HD]  10.48 21.8 270 top
C4604  10 uF  [CAP0603-HT1_HD]  5.69 17.25 0 top
C4605  10 uF  [CAP0603-HT1_HD]  5.69 16.09 0 top
C4606  0.00015 uF  [CAP0201-HT0_33_HD]  11.74 13.43 270 top
C4607  0.00015 uF  [CAP0201-HT0_33_HD]  12.63 13.75 270 top
C4608  33PF  [CAP0201-HT0_33_HD]  12.63 12.62 90 top
C4609  33PF  [CAP0201-HT0_33_HD]  11.74 12.48 90 top
C4610  10uF  [CAP1_2X0_7_HD]  10.93 20.95 180 top
C4618  1 uF  [CAP0201-HT0_35_HD]  10.86 15.79 180 top
C4670  18PF  [CAP0201-HT0_33_HD]  36.17 12.54 90 bottom
C4671  0.00015 uF  [CAP0201-HT0_33_HD]  36.67 12.54 90 bottom
C4672  18PF  [CAP0201-HT0_33_HD]  38.09 12.54 90 bottom
C4673  0.00015 uF  [CAP0201-HT0_33_HD]  37.59 12.54 90 bottom
C4674  18PF  [CAP0201-HT0_33_HD]  15.85 15.16 0 top
C4675  18PF  [CAP0201-HT0_33_HD]  16.94 15.16 180 top
C4790  15PF  [CAP0201-HT0_33_HD]  37.13 13.33 180 bottom
C5001  .1UF  [CAP0201-HT0_33_HD]  57.07 58.78 0 top
C5002  1 uF  [CAP0201_HD]  57.56 61.01 180 top
C5306  100PF  [CAP0201-HT0_33_HD]  55.12 61.85 90 top
C5307  .1UF  [CAP0201-HT0_33_HD]  52.86 64.76 90 bottom
C5308  100PF  [CAP0201-HT0_33_HD]  56.97 64.77 90 bottom
C5310  100PF  [CAP0201-HT0_33_HD]  53.47 64.76 90 bottom
C5311  .1UF  [CAP0201-HT0_33_HD]  51.86 64.77 90 bottom
C5313  18PF  [CAP0201-HT0_33_HD]  58.98 64.78 90 bottom
C5316  100PF  [CAP0201-HT0_33_HD]  57.98 64.77 90 bottom
C5317  .1UF  [CAP0201-HT0_33_HD]  58.2 62.08 90 top
C5318  100PF  [CAP0201-HT0_33_HD]  52.36 64.77 90 bottom
C5319  100PF  [CAP0201-HT0_33_HD]  55.97 64.76 90 bottom
C5320  18PF  [CAP0201-HT0_33_HD]  54.97 64.76 90 bottom
C5321  18PF  [CAP0201-HT0_33_HD]  53.97 64.76 90 bottom
C5322  100PF  [CAP0201-HT0_33_HD]  58.48 64.78 90 bottom
C5323  .1UF  [CAP0201-HT0_33_HD]  60.64 63.59 90 top
C5369  100PF  [CAP0201-HT0_33_HD]  59.98 64.78 90 bottom
C5370  18PF  [CAP0201-HT0_33_HD]  60.98 64.65 90 bottom
C5374  100PF  [CAP0201-HT0_33_HD]  51.36 64.77 90 bottom
C5382  100PF  [CAP0201-HT0_33_HD]  50.6 64.97 0 bottom
C5387  100PF  [CAP0201-HT0_33_HD]  57.47 64.77 90 bottom
C5500  18PF  [CAP0201-HT0_33_HD]  54.11 62.31 90 top
C5501  18PF  [CAP0201-HT0_33_HD]  54.61 62.31 90 top
C5502  18PF  [CAP0201-HT0_33_HD]  59.21 64.33 180 top
C5503  18PF  [CAP0201-HT0_33_HD]  12.98 68.18 270 top
C5504  100PF  [CAP0201-HT0_33_HD]  55.46 64.33 180 top
C5505  10PF  [CAP0201-HT0_33_HD]  26.97 63.95 180 top
C5506  10PF  [CAP0201-HT0_33_HD]  26.97 64.46 180 top
C5507  100PF  [CAP0201-HT0_33_HD]  53.62 64.33 0 top
C5508  100PF  [CAP0201-HT0_33_HD]  57.36 64.33 0 top
C5509  100PF  [CAP0201-HT0_33_HD]  27.35 67 270 top
C5510  100PF  [CAP0201-HT0_33_HD]  32.62 64.37 180 top
C5511  100PF  [CAP0201-HT0_33_HD]  31.71 64.36 180 top
C5512  100PF  [CAP0201-HT0_33_HD]  54.53 64.33 180 top
C5513  100PF  [CAP0201-HT0_33_HD]  51.79 64.33 0 top
C5514  18PF  [CAP0201-HT0_33_HD]  13.48 68.17 270 top
C5515  100PF  [CAP0201-HT0_33_HD]  16.67 64.32 180 top
C5516  18PF  [CAP0201-HT0_33_HD]  35.67 64.37 180 top
C5517  18PF  [CAP0201-HT0_33_HD]  34.31 64.37 0 top
C5518  18PF  [CAP0201-HT0_33_HD]  11.37 68.18 270 top
C5519  18PF  [CAP0201-HT0_33_HD]  11.88 68.18 270 top
C5520  100PF  [CAP0201-HT0_33_HD]  12.39 68.18 270 top
C5521  18PF  [CAP0201-HT0_33_HD]  36.63 64.37 180 top
C5524  100PF  [CAP0201-HT0_33_HD]  19.07 64.51 90 top
C5528  18PF  [CAP0201-HT0_33_HD]  39.81 64.34 180 top
C5529  18PF  [CAP0201-HT0_33_HD]  38.9 64.33 180 top
C5530  18PF  [CAP0201-HT0_33_HD]  52.71 64.33 0 top
C5531  100PF  [CAP0201-HT0_33_HD]  15.75 64.32 180 top
C5532  100PF  [CAP0201-HT0_33_HD]  14.78 64.32 0 top
C5533  100PF  [CAP0201-HT0_33_HD]  13.86 64.32 0 top
C5534  100PF  [CAP0201-HT0_33_HD]  12.95 64.32 0 top
C5535  100PF  [CAP0201-HT0_33_HD]  12.02 64.31 0 top
C5536  100PF  [CAP0201-HT0_33_HD]  15.1 68.17 270 top
C5537  100PF  [CAP0201-HT0_33_HD]  14.6 68.17 270 top
C5538  100PF  [CAP0201-HT0_33_HD]  14.1 68.17 270 top
C5539  100PF  [CAP0201-HT0_33_HD]  56.38 64.33 0 top
C5541  100PF  [CAP0201-HT0_33_HD]  31.71 67.91 0 top
C5542  100PF  [CAP0201-HT0_33_HD]  30.8 67.91 180 top
C5549  100PF  [CAP0201-HT0_33_HD]  29.89 67.91 180 top
C5550  100PF  [CAP0201-HT0_33_HD]  28.98 67.91 180 top
C5551  100PF  [CAP0201-HT0_33_HD]  28.07 67.91 180 top
C5620  33PF  [CAP0201-HT0_33_HD]  28.94 64.16 180 top
C5680  33PF  [CAP0201-HT0_33_HD]  30.77 64.16 180 top
C6110  .1UF  [CAP0201-HT0_33_HD]  63.79 60.29 90 top
C6115  .1UF  [CAP0201-HT0_33_HD]  50.88 41.36 0 top
C6130  .1UF  [CAP0201-HT0_33_HD]  64.84 38.78 90 top
C6140  .1UF  [CAP0201-HT0_33_HD]  9.64 67.94 180 top
C6150  1 uF  [CAP0201_HD]  12.33 19.67 180 top
C6151  .1UF  [CAP0201-HT0_33_HD]  11.87 19.17 0 top
C6152  100PF  [CAP0201-HT0_33_HD]  11.87 18.66 0 top
C6153  100PF  [CAP0201-HT0_33_HD]  13.62 15.6 90 top
C6154  18PF  [CAP0201-HT0_33_HD]  13.11 18.82 270 top
C6155  18PF  [CAP0201-HT0_33_HD]  13.61 18.82 270 top
C6180  .1UF  [CAP0201-HT0_33_HD]  5.76 59.8 180 top
C6181  33PF  [CAP0201-HT0_33_HD]  4.68 56.56 90 top
C6183  .1UF  [CAP0201-HT0_33_HD]  6.23 50.18 180 top
C6184  .1UF  [CAP0201-HT0_33_HD]  5.34 52.81 0 top
C6241  1 uF  [CAP0201_HD]  5.4 56.74 0 top
C6242  1 uF  [CAP0201_HD]  5.98 51.94 90 top
C6243  1 uF  [CAP0201_HD]  5.25 54.77 90 top
C6244  1 uF  [CAP0201_HD]  6.34 56.23 0 top
C6245  4.7 uF  [CAP0402-HT0_55_HD]  8.49 56.19 270 top
C6260  4.7 uF  [CAP0402-HT0_55_HD]  11.52 56.18 270 top
C6261  1 uF  [CAP0201_HD]  13.25 53.81 180 top
C6262  1 uF  [CAP0201_HD]  8.77 50.35 180 top
C6263  1 uF  [CAP0201_HD]  13.58 53.05 270 top
C6264  1 uF  [CAP0201_HD]  10.85 50.35 0 top
C6265  4.7 uF  [CAP0402-HT0_55_HD]  9.24 56.19 270 top
C6266  2.2UF  [CAP0402-HT0_55_HD]  6.31 53.11 90 top
C6267  1 uF  [CAP0201_HD]  6.27 54.13 0 top
C6268  1 uF  [CAP0201_HD]  13.24 54.56 180 top
C6269  .1UF  [CAP0201-HT0_33_HD]  7.24 50.35 180 top
C6270  .1UF  [CAP0201-HT0_33_HD]  13.05 52.01 270 top
C6271  .1UF  [CAP0201-HT0_33_HD]  9.91 50.35 0 top
C6272  .22UF  [CAP0201-HT0_33_HD]  6.12 55.18 0 top
C6273  .22UF  [CAP0201-HT0_33_HD]  6.12 54.68 0 top
C6274  .22UF  [CAP0201-HT0_33_HD]  6.25 51.21 0 top
C6275  .22UF  [CAP0201-HT0_33_HD]  6.25 50.7 0 top
C6276  .22UF  [CAP0201-HT0_33_HD]  6.34 55.71 0 top
C6277  .22UF  [CAP0201-HT0_33_HD]  6.34 56.74 0 top
C6282  2.2UF  [CAP0402-HT0_55_HD]  8.64 57.62 270 top
C6283  4.7 uF  [CAP0402-HT0_55_HD]  9.71 57.28 180 top
C6284  4.7 uF  [CAP0402-HT0_55_HD]  7.74 56.19 90 top
C6285  2.2UF  [CAP0402-HT0_55_HD]  10.74 56.19 270 top
C6286  .47UF  [CAP0201-HT0_33_HD]  6.48 51.94 90 top
C6287  4.7 uF  [CAP0402-HT0_55_HD]  9.99 56.19 90 top
C6288  4.7 uF  [CAP0402-HT0_55_HD]  11.11 57.28 0 top
C6289  .22UF  [CAP0201-HT0_33_HD]  5.35 53.95 0 top
C6290  .22UF  [CAP0201-HT0_33_HD]  5.35 53.43 0 top
C6291  2.2UF  [CAP0402-HT0_55_HD]  15.93 50.85 270 top
C6292  4.7 uF  [CAP0402-HT0_55_HD]  7.89 57.62 90 top
C6293  4.7 uF  [CAP0402-HT0_55_HD]  13.51 50.73 90 top
C6295  .22UF  [CAP0201-HT0_33_HD]  5.41 55.7 0 top
C6296  .22UF  [CAP0201-HT0_33_HD]  5.4 56.23 0 top
C6400  100PF  [CAP0201-HT0_33_HD]  12.62 25.41 270 top
C6401  .1UF  [CAP0201-HT0_33_HD]  13.13 25.4 270 top
C6402  10uF  [CAP1_2X0_7_HD]  13.18 24.51 180 top
C6403  10 uF  [CAP0603-HT1_HD]  8.84 25.06 0 top
C6404  10 uF  [CAP0603-HT1_HD]  8.84 23.91 0 top
C6405  .1UF  [CAP0402-HT0_55_HD]  9.11 26.04 0 top
C6406  .47UF  [CAP0201-HT0_33_HD]  12.69 22.7 270 top
C6407  1 uF  [CAP0201-HT0_35_HD]  11.48 21.8 90 top
C6408  10 uF  [CAP0603-HT1_HD]  8.84 22.76 0 top
C6410  10uF  [CAP1_2X0_7_HD]  13.18 23.59 180 top
C6629  2.2 uF  [CAP0201_HD]  19.68 10.97 90 top
C6630  100PF  [CAP0201-HT0_33_HD]  20.2 10.97 90 top
C7003  22PF  [CAP0201-HT0_33_HD]  27.7 14.43 270 top
C7100  1000PF  [CAP0201-HT0_33_HD]  53.52 19.2 180 top
C7101  .1UF  [CAP0201-HT0_33_HD]  50.72 16.96 90 top
C7102  100PF  [CAP0201-HT0_33_HD]  50.2 16.96 90 top
C7103  4.7uF  [CAP0402_1_2X0_7_HD]  51.49 16.63 90 top
C7104  .1UF  [CAP0201-HT0_33_HD]  52.38 17.1 180 top
C7105  100PF  [CAP0201-HT0_33_HD]  52.38 16.6 180 top
C7106  33PF  [CAP0201-HT0_33_HD]  52.4 24.34 270 top
C7107  33PF  [CAP0201-HT0_33_HD]  51.67 24.2 180 top
C7109  100PF  [CAP0201-HT0_33_HD]  52.13 25.29 180 top
C7110  33PF  [CAP0201-HT0_33_HD]  53.52 20.24 180 top
C7112  100PF  [CAP0201-HT0_33_HD]  53.52 21.34 180 top
C7114  100PF  [CAP0201-HT0_33_HD]  53.39 22.57 270 top
C7126  7e-007 uF  [CAP0201-HT0_33_HD]  48.52 16.04 90 top
C7141  12PF  [CAP0201-HT0_33_HD]  46.23 16.57 0 top
C7149  100PF  [CAP0201-HT0_33_HD]  49.63 24.9 270 top
C7150  100PF  [CAP0201-HT0_33_HD]  36.4 25.41 180 top
C7151  1000PF  [CAP0201-HT0_33_HD]  34.68 25.56 270 top
C7152  .1UF  [CAP0201-HT0_33_HD]  36.4 25.91 180 top
C7154  33PF  [CAP0201-HT0_33_HD]  32.09 23 90 top
C7155  100PF  [CAP0201-HT0_33_HD]  32.09 24.84 270 top
C7157  100PF  [CAP0201-HT0_33_HD]  40.52 23.98 270 top
C7158  33PF  [CAP0201-HT0_33_HD]  39.65 23 90 top
C7160  1000PF  [CAP0201-HT0_33_HD]  37.14 25.58 270 top
C7161  100PF  [CAP0201-HT0_33_HD]  35.45 25.41 0 top
C7162  .1UF  [CAP0201-HT0_33_HD]  35.45 25.91 0 top
C7165  33PF  [CAP0201-HT0_33_HD]  33.6 25.71 270 top
C7170  33PF  [CAP0201-HT0_33_HD]  36.43 14.99 270 top
C7173  33PF  [CAP0201-HT0_33_HD]  38.58 15.37 90 top
C7181  15PF  [CAP0201-HT0_33_HD]  37.23 15.22 180 top
C7182  7e-007 uF  [CAP0201-HT0_33_HD]  37.22 14.72 180 top
C7199  100PF  [CAP0201-HT0_33_HD]  39.81 24.79 0 top
C7215  100PF  [CAP0201-HT0_33_HD]  28.25 31.88 90 top
C7216  1.8PF  [CAP0201-HT0_33_HD]  27.72 26.4 180 top
C7217  1.8PF  [CAP0201-HT0_33_HD]  28.64 26.4 0 top
C7218  .1UF  [CAP0201-HT0_33_HD]  26.03 23.97 270 top
C7219  100PF  [CAP0201-HT0_33_HD]  26.03 23.06 90 top
C7230  100PF  [CAP0201-HT0_33_HD]  48.4 24.18 0 top
C7234  100PF  [CAP0201-HT0_33_HD]  43.32 23.41 90 top
C7235  100PF  [CAP0201-HT0_33_HD]  43.83 23.41 90 top
C7238  .5PF  [CAP0201-HT0_33_HD]  43.94 19.7 0 top
C7241  100PF  [CAP0201-HT0_33_HD]  25.77 24.68 0 top
C7261  3.3 NH  [IND0201-HT0_35_HD]  47.4 25.05 0 top
C7264  1.8PF  [CAP0201-HT0_33_HD]  45.02 26.83 0 top
C7266  1.2PF  [CAP0201-HT0_33_HD]  46.65 26.53 270 top
C7267  100PF  [CAP0201-HT0_33_HD]  45.94 26.3 0 top
C7269  100PF  [CAP0201-HT0_33_HD]  27 26.35 270 top
C7270  100PF  [CAP0201-HT0_33_HD]  28.43 32.6 180 top
C7271  100PF  [CAP0201-HT0_33_HD]  26.48 26.35 270 top
C7273  .1UF  [CAP0201-HT0_33_HD]  25.77 25.19 0 top
C7274  100PF  [CAP0201-HT0_33_HD]  25.78 25.7 0 top
C7280  100PF  [CAP0201-HT0_33_HD]  29.55 25.89 180 top
C7285  100PF  [CAP0201-HT0_33_HD]  29.46 25.06 270 top
C7290  100PF  [CAP0201-HT0_33_HD]  46.27 24.33 90 top
C7300  33PF  [CAP0201-HT0_33_HD]  31.58 21.28 270 top
C7312  0  [RES0201-HT0_28_HD]  32.09 18.22 270 top
C7326  2.2PF  [CAP0201-HT0_33_HD]  29.7 30.91 270 top
C7327  33PF  [CAP0201-HT0_33_HD]  29.95 33.01 180 top
C7330  33PF  [CAP0201-HT0_33_HD]  31.55 30.92 270 top
C7332  33PF  [CAP0201-HT0_33_HD]  30.5 28.73 180 top
C7335  33PF  [CAP0201-HT0_33_HD]  27.21 28.28 90 top
C7351  18PF  [CAP0201-HT0_33_HD]  39.84 21.48 0 top
C7353  0  [RES0201-HT0_28_HD]  40.6 18.69 270 top
C7355  18PF  [CAP0201-HT0_33_HD]  39.83 18.15 180 top
C7366  .7NH  [IND0201-HT0_35_HD]  27.61 29.41 90 top
C7368  18PF  [CAP0201-HT0_33_HD]  29.36 28.39 180 top
C7369  18PF  [CAP0201-HT0_33_HD]  29.36 27.87 0 top
C7371  2.2PF  [CAP0201-HT0_33_HD]  28 27.33 180 top
C7376  2PF  [CAP0201-HT0_33_HD]  28.83 29.47 0 top
C7385  33PF  [CAP0201-HT0_33_HD]  29.59 32.06 0 top
C7386  33PF  [CAP0201-HT0_33_HD]  30.55 29.98 270 top
C7387  33PF  [CAP0201-HT0_33_HD]  30.49 29.25 0 top
C7388  33PF  [CAP0201-HT0_33_HD]  26.71 28.28 270 top
C7389  33PF  [CAP0201-HT0_33_HD]  28.83 28.96 0 top
C7390  33PF  [CAP0201-HT0_33_HD]  28.95 27.33 0 top
C7500  100PF  [CAP0201-HT0_33_HD]  19.31 23.41 180 top
C7501  100PF  [CAP0201-HT0_33_HD]  19.32 23.93 180 top
C7505  100PF  [CAP0201-HT0_33_HD]  16.05 23.85 90 top
C7510  33PF  [CAP0201-HT0_33_HD]  19.32 24.6 0 top
C7511  33PF  [CAP0201-HT0_33_HD]  19.32 25.11 0 top
C7515  3.3PF  [CAP0201-HT0_33_HD]  23.38 23.38 0 top
C7517  3.9PF  [CAP0201-HT0_33_HD]  22.16 23.63 270 top
C7520  18PF  [CAP0201-HT0_33_HD]  39.68 29.7 0 top
C7521  18PF  [CAP0201-HT0_33_HD]  39.66 30.23 0 top
C7526  18PF  [CAP0201-HT0_33_HD]  42.92 30.83 270 top
C7602  1.8NH  [IND0201-HT0_35_HD]  21.32 29.13 90 top
C7605  2.2NH  [IND0201-HT0_35_HD]  18.88 31.67 90 top
C7606  1.6NH  [IND0201-HT0_35_HD]  19.68 31.59 0 top
C7607  33PF  [CAP0201-HT0_33_HD]  21.32 28.2 270 top
C7608  33PF  [CAP0201-HT0_33_HD]  19.16 32.63 90 top
C7610  33PF  [CAP0201-HT0_33_HD]  21.76 25.72 90 top
C7613  33PF  [CAP0201-HT0_33_HD]  24.37 27.46 270 top
C7615  6.8NH  [IND0201-HT0_35_HD]  20.62 30.44 0 top
C7617  33PF  [CAP0201-HT0_33_HD]  19.69 30.53 180 top
C7620  33PF  [CAP0201-HT0_33_HD]  18.44 25.99 180 top
C7622  33PF  [CAP0201-HT0_33_HD]  20.23 25.82 90 top
C7625  2.2PF  [CAP0201-HT0_33_HD]  20.62 31.08 0 top
C7644  33PF  [CAP0201-HT0_33_HD]  20.71 29.85 0 top
C7645  33PF  [CAP0201-HT0_33_HD]  18.89 30.74 90 top
C7646  33PF  [CAP0201-HT0_33_HD]  24.19 28.46 90 top
C7647  33PF  [CAP0201-HT0_33_HD]  20.81 28.2 90 top
C7648  33PF  [CAP0201-HT0_33_HD]  19.69 31.08 0 top
C7700  .5PF  [CAP0201-HT0_33_HD]  17.06 26.21 270 top
C7701  4.7 uF  [CAP0402_1_2X0_7-HT0_65_HD]  17 34.52 180 top
C7702  100PF  [CAP0201-HT0_33_HD]  16.37 30.69 90 top
C7705  .5PF  [CAP0201-HT0_33_HD]  18.38 31.05 90 top
C7707  100PF  [CAP0201-HT0_33_HD]  16.97 33.63 180 top
C7711  22NH  [IND0201-HT0_35_HD]  17.17 30 180 top
C7712  100PF  [CAP0201-HT0_33_HD]  16.97 32.78 180 top
C7750  100PF  [CAP0201-HT0_33_HD]  21.54 32.15 0 top
C7751  100PF  [CAP0201-HT0_33_HD]  21.41 32.66 0 top
C7753  .1UF  [CAP0201-HT0_33_HD]  15.63 30.43 180 top
C7755  100PF  [CAP0201-HT0_33_HD]  15.63 30.93 180 top
C7760  1.8PF  [CAP0201-HT0_33_HD]  14.63 34.74 180 top
C7761  1.8PF  [CAP0201-HT0_33_HD]  15.57 34.74 0 top
C7767  .1UF  [CAP0201-HT0_33_HD]  14.2 30.4 0 top
C7768  100PF  [CAP0201-HT0_33_HD]  14.2 30.9 0 top
C7802  1PF  [CAP0201-HT0_33_HD]  36.75 28.66 90 top
C7822  15PF  [CAP0201-HT0_33_HD]  36.54 31.41 180 top
C7823  6.8NH  [IND0201-HT0_35_HD]  23.48 28.2 0 top
C7824  15PF  [CAP0201-HT0_33_HD]  22.53 28.18 180 top
C7830  15PF  [CAP0201-HT0_33_HD]  39.77 31.07 180 top
C7835  2.7NH  [IND0201-HT0_35_HD]  22.53 29.3 0 top
C7863  2.7NH  [IND0201-HT0_35_HD]  23.41 29.41 90 top
C7864  15PF  [CAP0201-HT0_33_HD]  35 28.42 180 top
C7867  1.8PF  [CAP0201-HT0_33_HD]  22.53 28.69 180 top
C7895  12PF  [CAP0201-HT0_33_HD]  22.53 29.8 180 top
C7896  12PF  [CAP0201-HT0_33_HD]  23.48 28.7 0 top
C8200  22 uF  [CAP0603-HT0_6_HD]  20.45 16.44 90 top
C8201  22 uF  [CAP0603-HT0_6_HD]  19.27 16.45 90 top
C8202  1 uF  [CAP0201_HD]  23.25 20.1 0 top
C8203  10 uF  [CAP0402_1_2X0_7-HT0_65_HD]  23.83 19.07 270 top
C8204  1 uF  [CAP0201_HD]  22.32 20.1 0 top
C8205  1 uF  [CAP0201_HD]  21.39 20.1 180 top
C8206  1 uF  [CAP0201_HD]  20.5 20.5 270 top
C8208  470PF  [CAP0201-HT0_33_HD]  22.3 16.56 270 top
C8209  4.7uF  [CAP0402-HT0_65_HD]  23 16.21 90 top
C8500  .1UF  [CAP0201-HT0_33_HD]  23.43 25.82 180 top
C8501  4.7PF  [CAP0201-HT0_33_HD]  24.64 25.3 0 top
C8503  33PF  [CAP0201-HT0_33_HD]  24.65 23.88 180 top
C8505  33PF  [CAP0201-HT0_33_HD]  23.87 26.55 270 top
C8507  4.7PF  [CAP0201-HT0_33_HD]  21.53 31.62 180 top
C8510  1PF  [CAP0201-HT0_33_HD]  24.65 23.37 0 top
C8516  33PF  [CAP0201-HT0_33_HD]  24.41 25.83 180 top
D350  -  [DIO0_6X0_3_PS0_525-HT0_33_HD]  10.11 68.18 180 bottom
D351  -  [DIO0_6X0_3_PS0_525-HT0_33_HD]  10.55 67.35 0 bottom
D352  -  [DIO0_6X0_3BI_HD]  6.33 64.4 180 bottom
D353  -  [DIO0_6X0_3BI_HD]  7.24 64.4 0 bottom
D354  -  [DIO0_6X0_3BI_HD]  8.54 68.49 90 bottom
D355  -  [DIO0_6X0_3BI_HD]  8.04 68.49 90 bottom
D356  -  [DIO0_6X0_3BI_HD]  7.54 68.49 90 bottom
D500  -  [DIO2SQ_PS1_3_P3_HD]  31.74 7.5 180 bottom
D501  -  [DIO0_6X0_3BI_PS0_38_HD]  36.3 3.85 90 bottom
D502  -  [DIO0_6X0_3BI_PS0_38_HD]  36.31 2.15 90 bottom
D503  -  [DIO0_6X0_3BI_PS0_38_HD]  35.81 2.15 90 bottom
D504  -  [DIO0_6X0_3BI_PS0_38_HD]  35.8 3.85 90 bottom
D505  -  [DIO0_6X0_3BI_PS0_38_HD]  34.66 7.91 0 bottom
D506  -  [DIO0_6X0_3BI_PS0_38_HD]  32.41 5.76 90 bottom
D507  -  [DIO0_6X0_3BI_PS0_38_HD]  32.5 2.25 90 bottom
D508  -  [DIO0_6X0_3BI_PS0_38_HD]  32.41 4.84 270 bottom
D509  -  [DIO0_6X0_3BI_PS0_38_HD]  32.41 3.97 90 bottom
D510  -  [DIO1X0_6_PS0_65_HD]  10.57 66.39 90 bottom
D511  -  [DIO0_6X0_3BI_PS0_38_HD]  35.95 5.93 90 bottom
D512  -  [DIO0_6X0_3BI_PS0_38_HD]  36.48 5.93 90 bottom
D513  -  [DIO1X0_6K1A2_PS0_65_HD]  31.7 10.8 90 bottom
D514  -  [DIO0_6X0_3BI_PS0_38_HD]  33.02 2.25 90 bottom
D516  -  [DIO0_6X0_3_PS0_4-HT0_32_HD]  31.23 5.8 90 bottom
D517  -  [DIO0_6X0_3_PS0_4-HT0_32_HD]  37.28 5.71 270 bottom
D518  -  [DIO1X0_6_PS0_65_HD]  16.51 66.6 90 bottom
D4250  -  [DIO0_6X0_3_PS0_38_HD]  58.71 44.78 315 bottom
D4251  -  [DIO0_6X0_3_PS0_38_HD]  59.34 44.24 180 bottom
D5301  -  [DIO0_6X0_3_PS0_38_HD]  61.48 64.7 90 bottom
D5302  -  [DIO0_6X0_3_PS0_38_HD]  60.48 64.7 90 bottom
E500  -  [IND0603_HD]  30.4 9.38 180 bottom
E510  0.001  [SD_L1]  8.11 64.01 0 top
E518  0.001  [SD_L1]  11.07 62.27 0 top
E519  0.001  [SD_L1]  10.55 62.43 0 top
E521  0.001  [SD_L1]  12.12 61.32 0 top
E1055  0.001  [SD_L1]  34.65 61.38 0 top
E1056  0.001  [SD_L1]  34.64 61.72 0 top
E1068  0.001  [SD_L1]  29.8 55.53 0 top
E1069  0.001  [SD_L1]  29.47 55.53 0 top
E1070  0.001  [SD_L1]  29.81 52.3 0 top
E1073  0.001  [SD_L1]  32.26 48.22 0 top
E1074  0.001  [SD_L1]  32.28 48.55 0 top
E1109  0.001  [SD_L1]  34.47 48.67 180 top
E1110  0.001  [SD_L1]  34.47 48.34 180 top
E1114  0.001  [SD_L1]  37.54 48.19 0 top
E1115  0.001  [SD_L1]  37.91 48.21 0 top
E1116  0.001  [SD_L1]  40.7 46.88 0 top
E1117  0.001  [SD_L1]  39.84 47.05 0 top
E1601  0.001  [SD_L1]  56.16 47.07 0 top
E2000_XOADC_GND  0.001  [SD_L1]  20.71 55.24 0 top
E2001  0.001  [SD_L1]  19.72 55.73 0 top
E2356  0.001  [SD_L1]  40.45 43.62 0 top
E2357  0.001  [SD_L1]  40.63 43.62 0 top
E2408  0.001  [SD_L1]  14.27 58.41 0 top
E2451  0.001  [SD_L1]  42.86 39.9 0 top
E2452  0.001  [SD_L1]  43.04 39.9 0 top
E2453  0.001  [SD_L1]  43.22 39.9 0 top
E2454  0.001  [SD_L1]  42.95 39.74 0 top
E2455  0.001  [SD_L1]  43.13 39.74 0 top
E2560  0.001  [SD_L1]  25.21 50.05 0 top
E2570  0.001  [SD_L1]  57.41 49.8 0 top
E4120  0.001  [SD_L1]  60.5 49.23 0 top
E4520  0.001  [SD_L1]  16.11 11.42 0 top
E4670  0.001  [SD_L1]  35.99 14.57 180 top
E4671  0.001  [SD_L1]  35.76 14.7 180 top
E5302  -  [IND0201-HT0_35_HD]  59.48 64.78 90 bottom
E5303  -  [IND0201-HT0_35_HD]  56.47 64.76 90 bottom
E5304  -  [IND0201-HT0_35_HD]  54.47 64.76 90 bottom
E5305  -  [IND0201-HT0_35_HD]  55.47 64.76 90 bottom
E5620  -  [IND0201-HT0_35_HD]  28.03 64.16 0 top
E5680  -  [IND0201-HT0_35_HD]  29.85 64.16 0 top
E6400_GNDA  0.001  [SD_L1]  10.77 22.48 270 top
E6400_GNDP1  0.001  [SD_L1]  8.32 23.82 0 top
E8200  -  [IND0201-HT0_33_HD]  21.3 16.35 270 top
FL500  0.13 uH  [IND0_5X0_65-HT0_35_P4_HD]  36.22 6.8 90 bottom
FL4040  -  [FLTR1_6X0_8-HT0_65_P3_HD]  46.41 33.97 180 top
FL4050  -  [FLTR1_6X0_8-HT0_65_P3_HD]  57.25 27.56 270 top
FL4060  -  [FLTR1_1X0_9_PS0_4X0_5_P5_HD]  60.04 26.45 270 top
FL4070  -  [FLTR1_1X0_9_PS0_4X0_5_P5_HD]  53.03 30.73 180 top
FL7001  -  [FLTR1_8X1_4_PS0_45_P10_HD]  29.52 16.17 90 top
FL7003  -  [FLTR2_5X2_PS0_65_P6_HD]  29.24 13.48 90 top
FL7030  -  [FLTR1_8X1_35-HT0_5_P10_HD]  40.71 16.1 180 top
FL7050  -  [FLTR1_6X0_8_PS0_5-HT0_7_P8_HD]  9.64 30.3 0 top
FL7141  -  [FLTR0_8X1_6_PS0_5-HT0_7_P6_HD]  49.14 13.26 180 bottom
FL7150  -  [FLTR1X0_5_P4_HD]  39.98 13.95 180 top
FL7170  -  [FLTR0_8X1_6_P4_HD]  37.98 13.77 270 top
FL7260  -  [FLTR1_8X1_4_PS0_65_P8_HD]  44.76 25.06 0 top
FL7300  -  [FLTR1_8X1_4_PS0_65_P8_HD]  32.7 13.98 0 top
FL7310  -  [FLTR1_8X1_4_PS0_65-HT0_48_P8_HD]  35 14.49 180 top
FL7350  -  [FLTR1_35X1_05CCW-HT0_5_P5_HD]  40.17 20.1 270 top
FL7600  -  [FLTR1_5X1_1_PS0_39-HT0_5_P10_HD]  19.25 29.39 0 top
FL7610  -  [FLTR1_5X1_1_PS0_39-HT0_5_P10_HD]  22.57 26.96 0 top
FL7620  -  [FLTR1_5X1_1_PS0_39-HT0_5_P10_HD]  19.49 27.08 180 top
FL7700  -  [FLTR1_1X0_9_PS0_4X0_5_P5_HD]  16.93 27.98 90 top
FL7705  -  [FLTR1_1X0_9_PS0_4X0_55_P5_HD]  18.12 33.24 90 top
FL7710  -  [FLTR1_1X0_9_PS0_4X0_55_P5_HD]  17.36 31.64 90 top
FL7715  -  [FLTR1_1X0_9-HT0_5_P5_HD]  15.44 27.98 90 top
FL7720  -  [FLTR1_1X0_9_PS0_4X0_5_P5_HD]  12.92 33.08 90 top
FL7800  -  [FLTR1_1X0_9_PS0_4X0_55_P5_HD]  37.85 28.8 180 top
FL7820  -  [FLTR1_1X0_9-HT0_5_P5_HD]  35.32 30.22 180 top
FL7830  -  [FLTR1_1X0_9_PS0_4X0_5_P5_HD]  37.85 30.79 180 top
FL8502  -  [FLTR1_1X0_9-HT0_5_P5_HD]  20.23 32.98 90 top
J110  -  [CSF1X2JSM_4G_PS1_55-HT0_9_P6_HD]  23.81 8.82 0 bottom
J130  -  [CSF1X2JSM_4G_PS1_55-HT0_9_P6_HD]  29.18 12.77 270 bottom
J210  -  [CSF1X2JSM_4G_PS1_55-HT0_9_P6_HD]  51.75 13.28 90 bottom
J230  -  [CSF1X2JSM_4G_PS1_55-HT0_9_P6_HD]  45.35 13.28 90 bottom
J250  -  [CSF1X2JSM_4G_PS1_55-HT0_9_P6_HD]  58.16 13.28 90 bottom
J300  -  [CSF1X2JSM_4G_PS1_55-HT0_9_P6_HD]  60.25 33.47 0 bottom
J350  -  [CSF2X5BH0_7_4G_PS0_35_P14_XD]  7.58 66.38 0 bottom
J400  -  [CSF1X2JSM_4G_PS1_55-HT0_9_P6_HD]  10.66 32.1 180 bottom
J510  -  [CSF2X3BH0_6_4G_PS0_8_P10_HD]  13.54 66.31 0 bottom
J4250  -  [CSF2X3BH0_7_4G_PS0_4-HT0_88_P10_HD]  56.59 43.42 135 bottom
J4500  -  [CSF2X3BH0_6_4G_PS0_35_P10_XD]  15.61 9.18 0 top
J4700  -  [CSF2X3BH0_6_4G_PS0_35_P10_XD]  8.74 7.35 170 top
J5300  -  [CSF2X25BH0_7_8G_PS0_35_P58_XD]  54.09 66.48 180 bottom
J5500  -  [CSF2X30BH0_7_8G_PS0_35_P68_XD]  34.39 66.14 180 top
J5501  -  [CSF2X15BH0_7_PS0_35_P38_XD]  55.4 66.14 180 top
J5502  -  [CSF2X15BH0_7_PS0_35_P38_XD]  13.38 66.14 180 top
J6400  -  [CSF2X3BH1_4G_PS0_35_P10_XD]  37.14 9.03 180 bottom
J6601  -  [CSF1X6_1X7R_PS0_6-HT2_14_P13_HD]  23.46 11.75 90 top
JTAG  -  [CSF2X8BH0_98_2G_PS0_4-HT1_08_P18_HD]  44.94 46.89 180 bottom
L111  0.056 uH  [IND0201-HT0_35_HD]  23.31 10.53 0 bottom
L113  7.5NH  [IND1005-HT0_6_HD]  12.49 7.93 90 bottom
L116  2.4e-006 uF  [CAP0402-HT0_55_HD]  12.56 10.74 270 bottom
L117  2.4NH  [IND1005-HT0_6_HD]  9.53 10.86 270 bottom
L118  16NH  [IND1005-HT0_6_HD]  9.21 9.7 0 bottom
L122  3.9e-006 uF  [CAP0402-HT0_55_HD]  8.39 8.19 180 bottom
L123  3.4NH  [IND1005-HT0_6_HD]  8.39 8.95 180 bottom
L124  1.5PF  [CAP0201-HT0_33_HD]  8.05 9.93 0 bottom
L131  0.056 uH  [IND0201-HT0_35_HD]  30.83 12.64 90 bottom
L142  0  [RES0402-HT0_4_HD]  10.71 12.24 180 bottom
L143  8.2NH  [IND1005-HT0_6_HD]  10.71 12.99 180 bottom
L144  4.6e-006 uF  [CAP0402-HT0_55_HD]  9.32 12.22 180 bottom
L170  3.4NH  [IND1005-HT0_6_HD]  8.25 12.59 270 bottom
L171  0  [RES0402-HT0_4_HD]  8.36 11.42 180 bottom
L175  270NH  [INDP0402-HT0_55_HD]  10.22 11.69 0 top
L177  22NH  [IND0201-HT0_35_HD]  11.37 11.67 180 top
L211  0.056 uH  [IND0201-HT0_35_HD]  50.09 13.73 270 bottom
L214  2.7e-006 uF  [CAP0402-HT0_55_HD]  57.17 17.11 180 top
L216  2.2e-006 uF  [CAP0402-HT0_55_HD]  55.71 19.31 270 top
L217  1.8e-006 uF  [CAP0402-HT0_55_HD]  58.64 19.78 270 top
L218  8.2NH  [IND1005-HT0_6_HD]  58.66 18.33 270 top
L222  2.4NH  [IND1005-HT0_6_HD]  58.9 16.32 0 top
L223  91NH  [IND1005-HT0_6_HD]  60.29 16.32 180 top
L224  1.5PF  [CAP0201-HT0_33_HD]  60.22 15.5 270 top
L231  0.056 uH  [IND0201-HT0_35_HD]  43.69 13.73 270 bottom
L242  1.5e-006 uF  [CAP0402-HT0_55_HD]  56.03 15.04 0 top
L243  5e-007 uF  [CAP0402-HT0_55_HD]  56.03 15.8 0 top
L244  1.5NH  [IND1005-HT0_6_HD]  57.47 15.8 0 top
L251  0.056 uH  [IND0201-HT0_35_HD]  56.36 13.06 0 bottom
L262  5e-007 uF  [CAP0402-HT0_55_HD]  60.24 13.19 180 top
